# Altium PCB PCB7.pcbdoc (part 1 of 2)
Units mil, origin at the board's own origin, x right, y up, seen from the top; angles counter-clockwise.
Board outline 4082.91 x 5474.41 mil, 4 copper layers (Top Layer, Inner1, Inner2, Bottom Layer); 133 components, 162 nets, 570 pads, 328 vias.
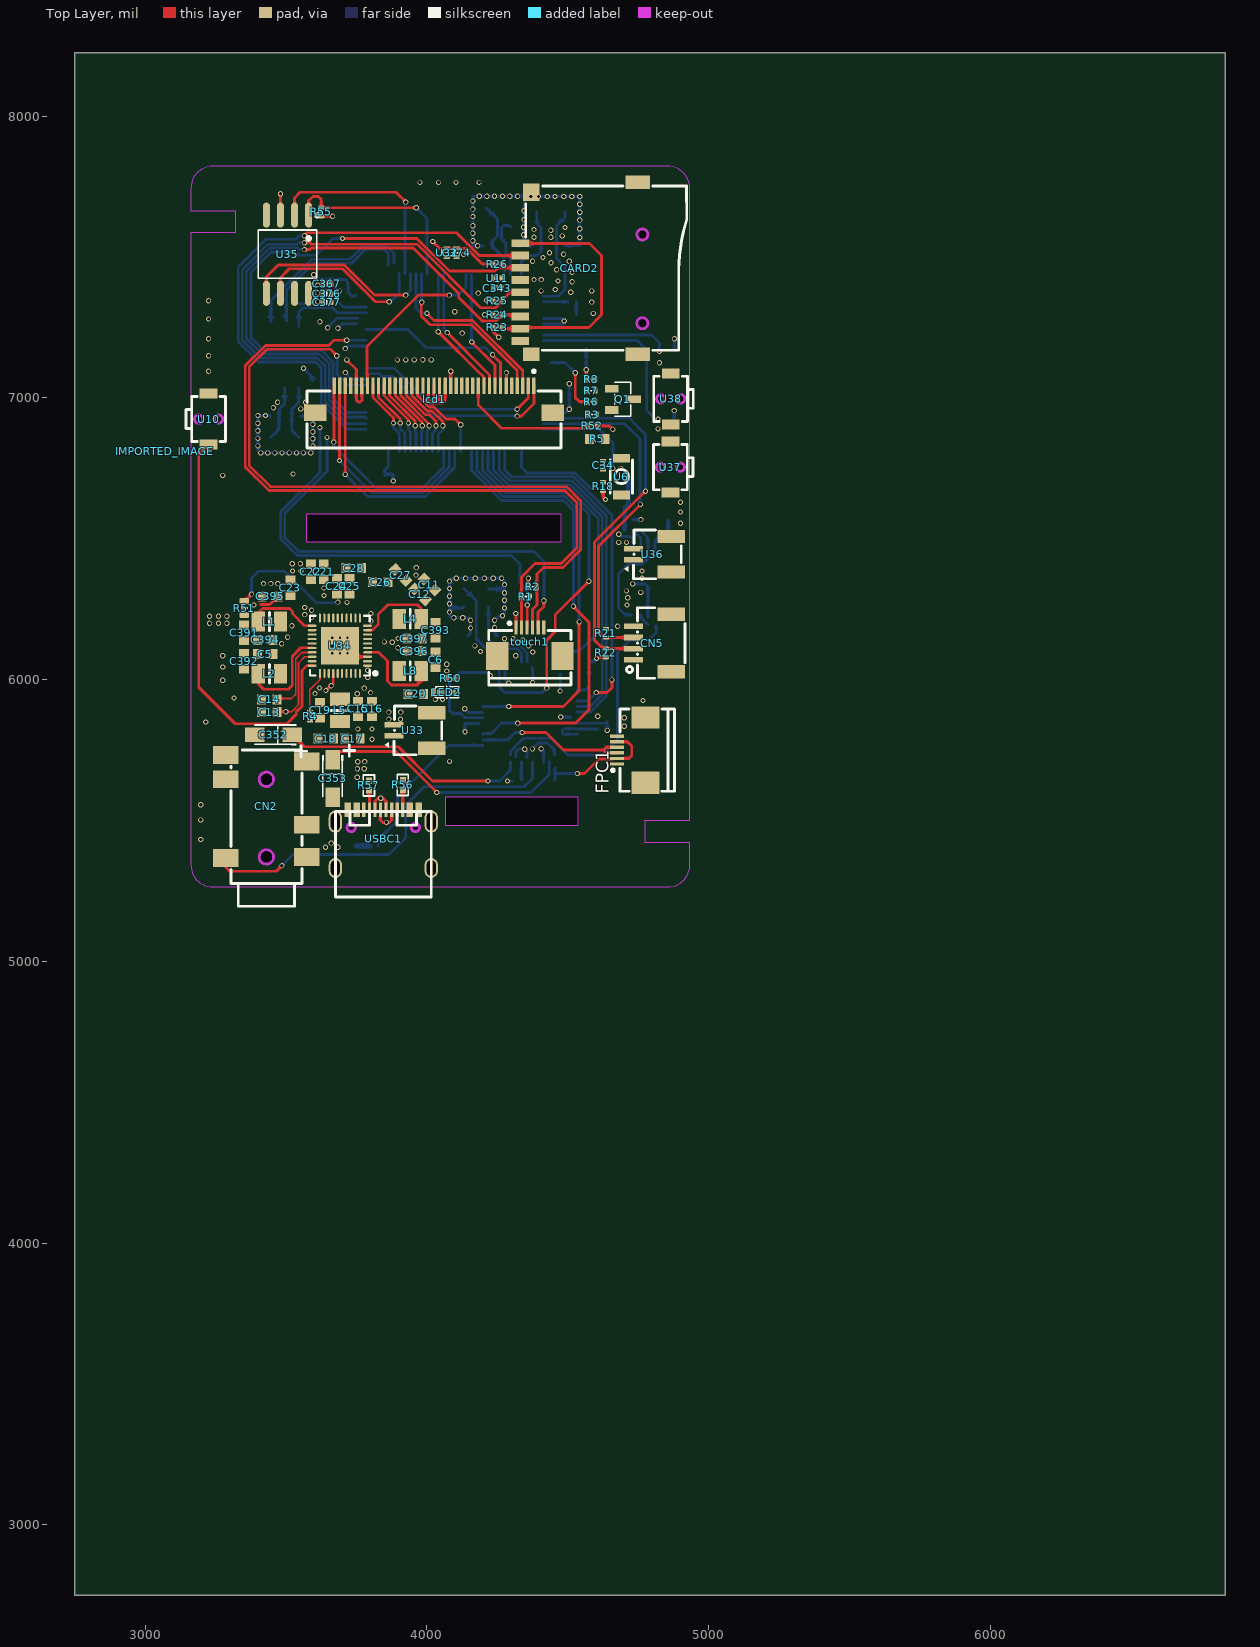
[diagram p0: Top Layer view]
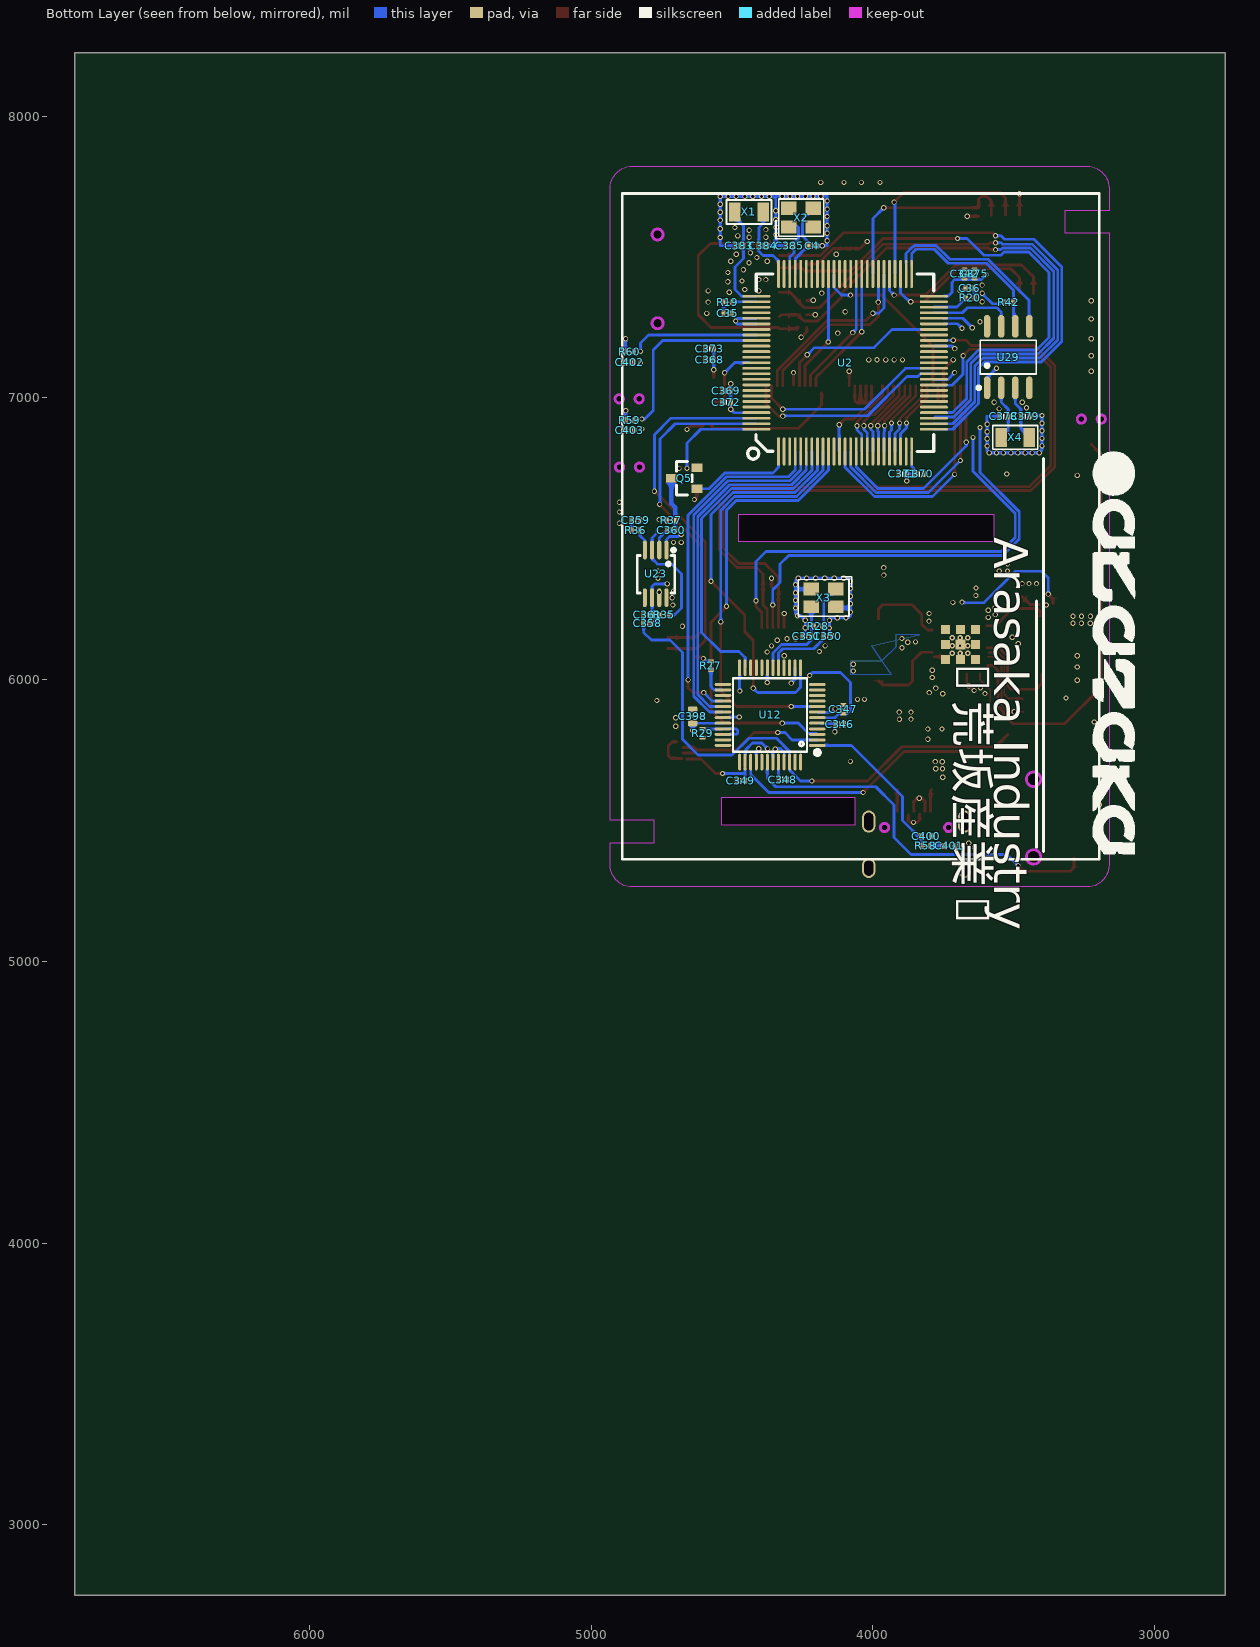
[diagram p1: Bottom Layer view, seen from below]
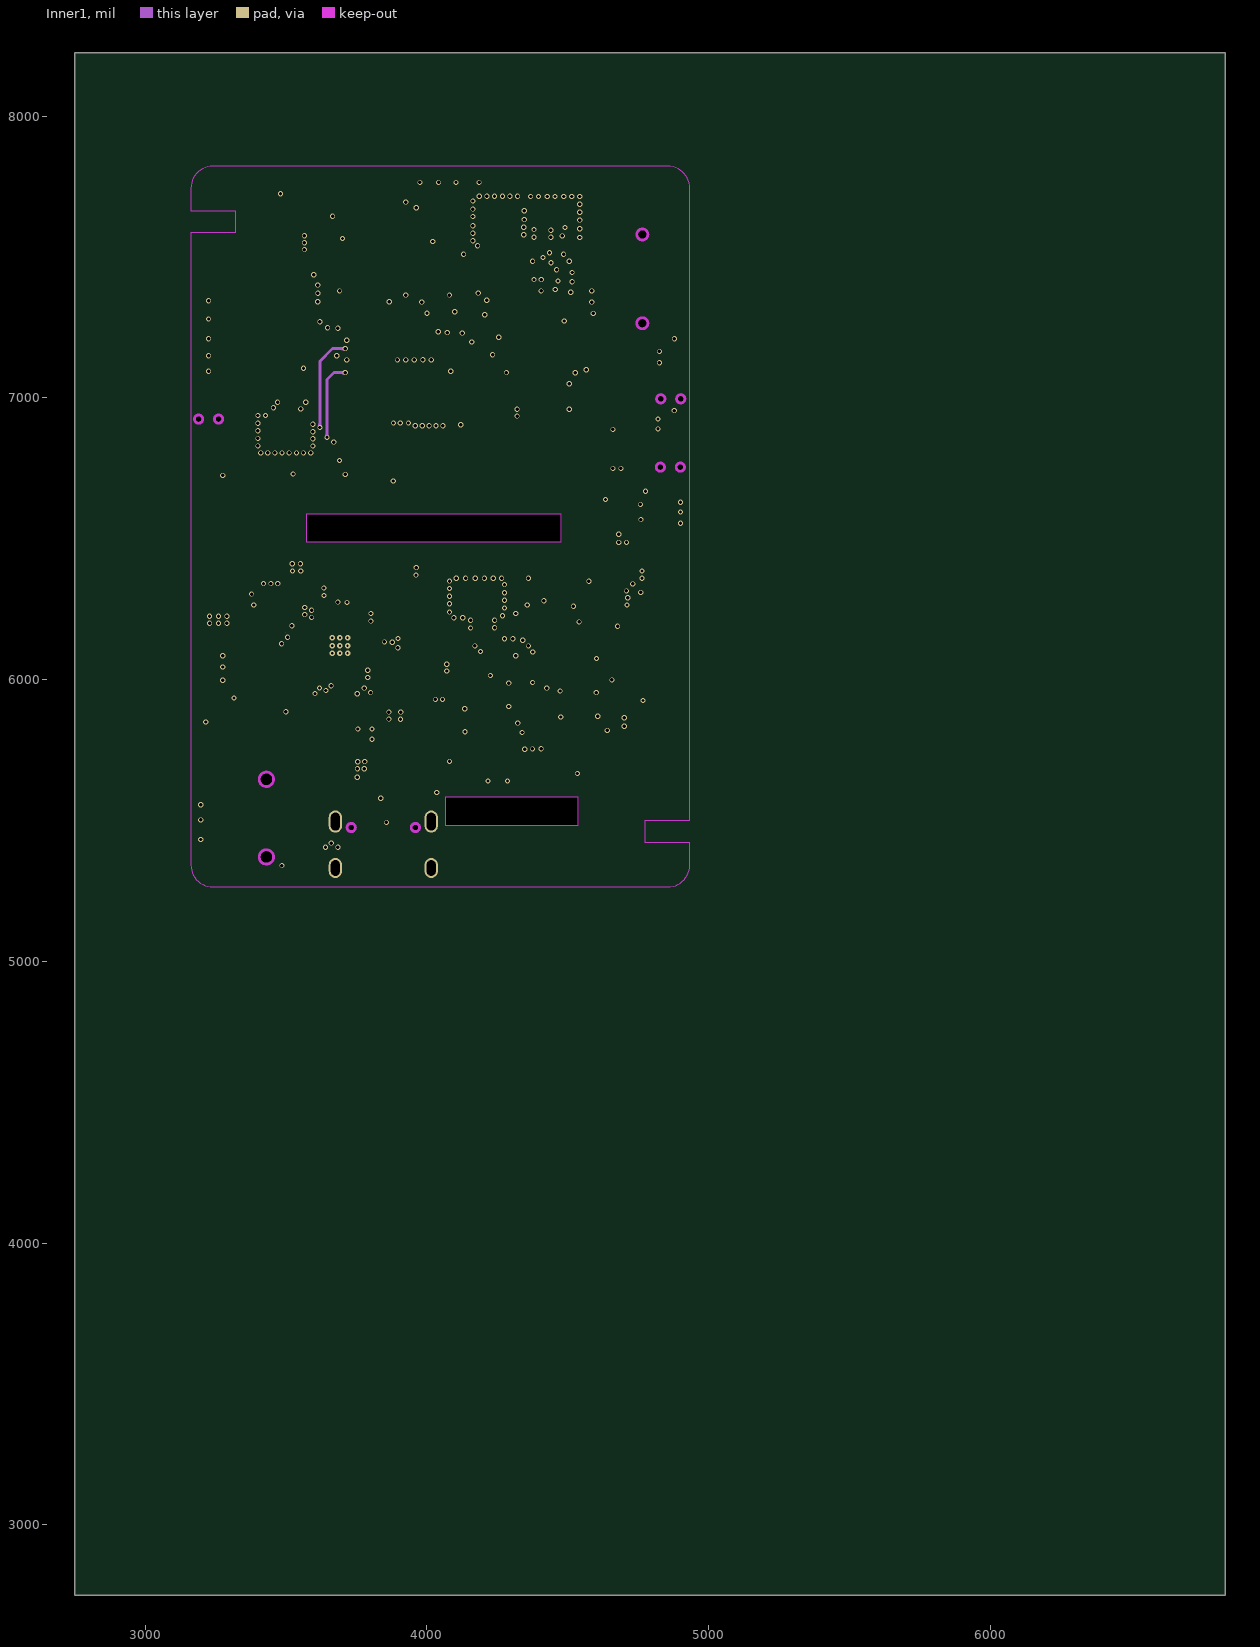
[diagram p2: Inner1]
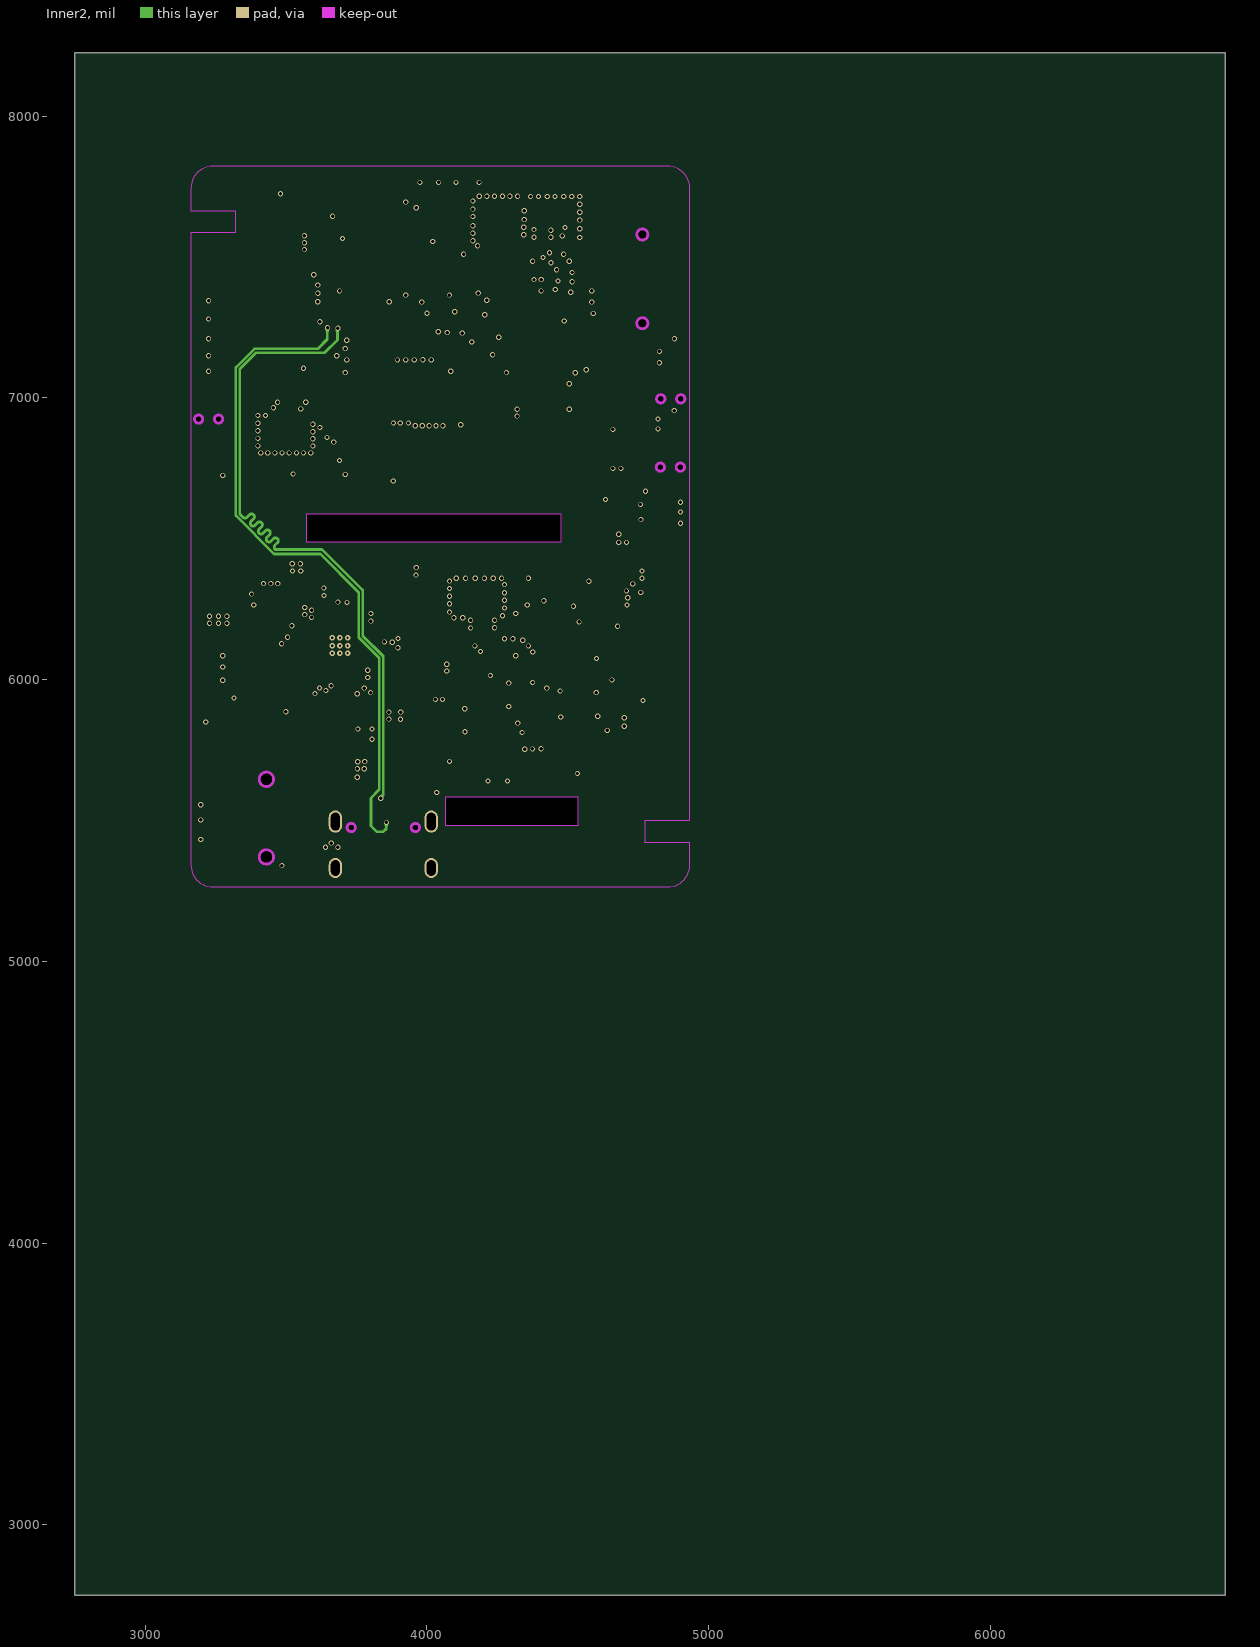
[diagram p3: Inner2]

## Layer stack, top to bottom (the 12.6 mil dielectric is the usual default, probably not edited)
Top Layer: signal copper (thickness not stored)
Dielectric: dielectric 12.6, FR-4, Dk 4.8
Inner1: signal copper (thickness not stored)
Dielectric: dielectric 12.6, FR-4, Dk 4.8
Inner2: signal copper (thickness not stored)
Dielectric: dielectric 12.6, FR-4, Dk 4.8
Bottom Layer: signal copper (thickness not stored)

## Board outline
6832.91,2750 2750,2750 2750,8224.41 6832.91,8224.41
cut-out: 4536.56,5581.38 4064.11,5581.38 4064.11,5482.95 4536.56,5482.95
cut-out: 4476.46,6586.51 3570.95,6586.51 3570.95,6488.08 4476.46,6488.08

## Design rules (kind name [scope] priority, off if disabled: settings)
Clearance copperThickness1oz [All] p1: gap=7 ignorepadtopadclearanceinfootprint=FALSE except(0: SMDPad-Via THPad-Via; 4: Track-Track; 6: Track-SMDPad SMDPad-SMDPad Track-THPad SMDPad-THPad THPad-THPad Track-Via Via-Via SMDPad-Fill THPad-Fill Via-Fill Fill-Fill Track-Region SMDPad-Region THPad-Region Via-Region Region-Region Track-Poly SMDPad-Poly THPad-Poly Via-Poly Fill-Poly Region-Poly Poly-Poly Track-Text SMDPad-Text THPad-Text Via-Text Fill-Text Region-Text Poly-Text Text-Text; 6.9: Track-Hole SMDPad-Hole THPad-Hole Via-Hole Fill-Hole Region-Hole Poly-Hole Text-Hole Sheet-Hole; 11.8: Track-Fill Fill-Region Track-Sheet SMDPad-Sheet THPad-Sheet Via-Sheet Fill-Sheet Region-Sheet Poly-Sheet Text-Sheet)
Clearance copperThickness2oz [All] p1: gap=7 ignorepadtopadclearanceinfootprint=FALSE except(6: Track-SMDPad SMDPad-SMDPad Track-THPad SMDPad-THPad THPad-THPad Track-Via SMDPad-Via THPad-Via Via-Via SMDPad-Fill THPad-Fill Via-Fill Fill-Fill Track-Region SMDPad-Region THPad-Region Via-Region Region-Region Track-Poly SMDPad-Poly THPad-Poly Via-Poly Fill-Poly Region-Poly Poly-Poly Track-Text SMDPad-Text THPad-Text Via-Text Fill-Text Region-Text Poly-Text Text-Text; 6.9: Track-Hole SMDPad-Hole THPad-Hole Via-Hole Fill-Hole Region-Hole Poly-Hole Text-Hole Sheet-Hole; 8: Track-Track; 11.8: Track-Fill Fill-Region Track-Sheet SMDPad-Sheet THPad-Sheet Via-Sheet Fill-Sheet Region-Sheet Poly-Sheet Text-Sheet)
DiffPairsRouting differentialPair [All] p1: maxuncoupledlength=10 maxlimit=6 mostfreqgap=6 toplayer_minwidth=5 toplayer_prefwidth=10 toplayer_maxwidth=100 bottomlayer_minwidth=5 bottomlayer_prefwidth=10 bottomlayer_maxwidth=100 midlayer1_minwidth=5 midlayer1_prefwidth=10 midlayer1_maxwidth=100 midlayer2_minwidth=5 midlayer2_prefwidth=10 midlayer2_maxwidth=100
PasteMaskExpansion pasteMaskExpansion [All] p1:
PlaneConnect innerPlane [All] p1: planeconnectstyle=Relief reliefexpansion=20 reliefentries=4 reliefconductorwidth=10 reliefairgap=10
PolygonConnect copperRegion [All] p1: connectstyle=Direct reliefentries=4 reliefconductorwidth=10 polygonreliefangle="90 Angle" airgapwidth=10
RoutingVias viaSize [All] p1: viastyle="Through Hole" holewidth=12 minholewidth=7 maxholewidth=248 width=18.5 minwidth=7 maxwidth=393.7
SolderMaskExpansion solderMaskExpansion [All] p1: useseparateexpansions=TRUE expansion=2 expansionbottom=2
Width copperThickness1oz [All] p1: maxlimit=100 minlimit=5 preferedwidth=10
Width copperThickness2oz [All] p1: maxlimit=100 minlimit=8 preferedwidth=10

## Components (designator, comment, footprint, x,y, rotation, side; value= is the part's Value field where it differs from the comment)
C4 "GRM1555C1H120JA01D" C0402-NSK#1 4215,7539.41 r180 bottom
C5 "CL10A225KP8NNNC" C0603 3425.63,6090.47 r180 top
C6 "CL10A226MQ8NRNC" C0603 4030.63,6070.47 r90 top
C11 "CL10A225KP8NNNC" C0603 4008.64,6337.2 r315 top
C12 "CL10A225KP8NNNC" C0603 3975.05,6302.2 r315 top
C13 "CL10A225KP8NNNC" C0603 3440,5884.41 r180 top
C14 "CL10A225KP8NNNC" C0603 3440,5929.41 r180 top
C15 "CL10A106KP8NNNC" C0603 3755.63,5895.47 r270 top
C16 "CL10A106KP8NNNC" C0603 3805.63,5895.47 r270 top
C17 "CL10B104KB8NNNC" C0603 3735.69,5790.3 r180 top
C18 "CL10A226MQ8NRNC" C0603 3640.63,5790.47 r0 top
C19 "CL10A225KP8NNNC" C0603 3620.63,5890.47 r90 top
C20 "CL10A105KO8NNNC" C0603 3960,5949.41 r180 top
C21 "CL10A225KP8NNNC" C0603 3633.64,6382.13 r270 top
C22 "CL10A225KP8NNNC" C0603 3588.07,6383.03 r270 top
C23 "CL10A225KP8NNNC" C0603 3515.63,6325.47 r90 top
C24 "CL10A225KP8NNNC" C0603 3680.63,6330.47 r270 top
C25 "CL10A225KP8NNNC" C0603 3725.63,6330.47 r270 top
C26 "CL10A475KP8NNNC" C0603 3834.09,6345.85 r180 top
C27 "CL10A225KP8NNNC" C0603 3906.66,6370.6 r315 top
C28 "CL10A225KP8NNNC" C0603 3740.63,6395.47 r0 top
C34 "CAP_0402" C0402-NSK#2 4624.79,6760.25 r270 top
C35 "CL05A105KA5NQNC" C0402-NSK#1 4515,7299.41 r0 bottom
C36 "CL05A105KA5NQNC" C0402-NSK#1 3655.63,7389.41 r180 bottom
C342 "CL05B104KB54PNC" C0402-NSK#1 3675,7439.41 r270 bottom
C343 "CL05B104KB54PNC" C0402-NSK#2 4250,7389.41 r0 top
C346 "CAP_0402" C0402-NSK#1 4117.33,5840.96 r0 bottom
C347 "CAP_0402" C0402-NSK#1 4105,5894.41 r270 bottom
C348 "CAP_0402" C0402-NSK#1 4320,5644.41 r180 bottom
C349 "CL05B103KB5NNNC" C0402-NSK#1 4468.65,5640.27 r0 bottom
C350 "GRM1555C1H120JA01D" C0402-NSK#1 4160,6154.41 r0 bottom
C351 "GRM1555C1H120JA01D" C0402-NSK#1 4235,6154.41 r180 bottom
C352 "TAJA106K016RNJ" CAP-SMD_L3.2-W1.6-RD-C7171 3455,5804.41 r180 top
C353 "TAJA106K016RNJ" CAP-SMD_L3.2-W1.6-RD-C7171 3665,5649.41 r270 top
C358 "CL05B104KB54PNC" C0402-NSK#1 4800,6199.41 r180 bottom
C359 "CL05B104KB54PNC" C0402-NSK#1 4841.3,6565.01 r0 bottom
C360 "CL05A105KA5NQNC" C0402-NSK#1 4716.3,6530.01 r180 bottom
C361 "CL05A105KA5NQNC" C0402-NSK#1 4800,6229.41 r180 bottom
C367 "CL05B104KB54PNC" C0402-NSK#2 3645,7404.41 r180 top
C368 "CL05B104KB54PNC" C0402-NSK#1 4580,7134.41 r180 bottom
C369 "CL05B104KB54PNC" C0402-NSK#1 4520,7024.41 r180 bottom
C370 "CL05B104KB54PNC" C0402-NSK#1 3835,6729.41 r0 bottom
C371 "CL05B104KB54PNC" C0402-NSK#1 3894.74,6729.67 r180 bottom
C372 "CL05A106MQ5NUNC" C0402-NSK#1 4520,6984.41 r180 bottom
C373 "CL05B104KB54PNC" C0402-NSK#1 4580,7174.41 r180 bottom
C374 "CL05B104KB54PNC" C0402-NSK#2 4105,7514.41 r90 top
C375 "CL05B104KB54PNC" C0402-NSK#1 3640,7439.41 r270 bottom
C376 "CL05B104KB54PNC" C0402-NSK#2 3645,7369.41 r180 top
C377 "CL05B104KB54PNC" C0402-NSK#2 3645,7339.41 r180 top
C378 "GRM1555C1H120JA01D" C0402-NSK#1 3535,6934.41 r180 bottom
C379 "GRM1555C1H120JA01D" C0402-NSK#1 3460,6934.41 r0 bottom
C383 "GRM1555C1H120JA01D" C0402-NSK#1 4475,7539.41 r0 bottom
C384 "GRM1555C1H120JA01D" C0402-NSK#1 4390,7539.41 r180 bottom
C385 "GRM1555C1H120JA01D" C0402-NSK#1 4295,7539.41 r0 bottom
C391 "CL10A226MQ8NRNC" C0603 3350.63,6165.47 r270 top
C392 "CL10A226MQ8NRNC" C0603 3350.63,6065.47 r90 top
C393 "CL10A226MQ8NRNC" C0603 4030.63,6175.47 r270 top
C394 "CL10A225KP8NNNC" C0603 3425.63,6140.47 r180 top
C395 "CL10A225KP8NNNC" C0603 3443.13,6294.89 r0 top
C396 "CL10A225KP8NNNC" C0603 3955.63,6100.47 r0 top
C397 "CL10A225KP8NNNC" C0603 3955.63,6145.47 r0 top
C398 "CL10A105KB8NNNC" "C0603 NSK"#1 4640,5869.41 r270 bottom
C400 "CL05B103KB5NNNC" C0402-NSK#3 3810,5444.41 r0 bottom
C401 "CL05A105KA5NQNC" C0402-NSK#3 3730,5409.41 r180 bottom
C402 "CL05A105KA5NQNC" C0402-NSK#1 4863.92,7126.24 r180 bottom
C403 "CL05A105KA5NQNC" C0402-NSK#1 4862.64,6885.4 r180 bottom
CARD2 "TF-115-BCP9" TF-SMD_TF-115-BCP9 4540,7459.41 r90 top
CN2 "PJ-342_C668606" AUDIO-SMD_PJ-342 3430,5549.41 r180 top
CN5 "WAFER-SH1.0-4PWB" CONN-SMD_4P-P1.00_WAFER-SH1.0-4PWB 4800,6129.41 r90 top
FPC1 "FPC-05F-6PH20" FPC-SMD_6P-P0.50_XUNPU_FPC-05F-6PH20 4725,5749.41 r90 top
IMPORTED_IMAGE "IMPORTED_IMAGE" IMPORTED_IMAGE 3070,6809.41 r0 top
L1 "1uH" L0806 3440.63,6205.47 r180 top
L2 "1uH" L0806 3440.63,6020.47 r180 top
L4 "1uH" L0806 3940.63,6215.47 r0 top
L5 "1uH" L0806 3690.63,5890.47 r90 top
L8 "1uH" L0806 3940.63,6030.47 r0 top
lcd1 "KH-FG0.5-H2.0-37PIN" FPC-SMD_37P-P0.50_KINGHELM_KH-FG0.5-H2.0-37PIN 4025,6994.41 r0 top locked
LED2 "NCD0402R1" LED0402-RD 4070,5954.41 r0 top
Q1 "MMS8050-H-TP" SOT-23-3_L2.9-W1.3-P1.90-LS2.4-BR 4695,6994.41 r180 top
Q5 "AO3401A_C15127" SOT-23_L2.9-W1.3-P1.90-LS2.4-BR 4670,6714.41 r180 bottom
R1 "0402WGF1002TCE" R0402#1 4350,6294.41 r0 top
R2 "0402WGF1002TCE" R0402#1 4375,6329.41 r180 top
R3 "0402WGF0000TCE" R0402#1 4587.4,6940.31 r0 top
R4 "0402WGF2200TCE" R0402#1 3585,5869.41 r270 top
R5 "CR164R33F" C0603 4605,6854.41 r180 top
R6 "0402WGF1001TCE" R0402#1 4582.4,6985.31 r0 top
R7 "0402WGF1002TCE" R0402#1 4582.4,7025.31 r0 top
R8 "0402WGF1002TCE" R0402#1 4582.4,7065.31 r0 top
R18 "Res_0402" R0402#1 4624.79,6685.25 r270 top
R19 "RC0402FR-0747RL" R0402#1 4515.29,7339.41 r180 bottom
R20 "RC0402FR-0747RL" R0402#1 3655,7354.41 r0 bottom
R21 "0402WGF4701TCE" R0402#1 4635,6164.41 r90 top
R22 "0402WGF4701TCE" R0402#1 4635,6094.41 r270 top
R23 "0402WGF1002TCE" R0402#1 4250,7249.41 r180 top
R24 "0402WGF1002TCE" R0402#1 4250,7294.41 r180 top
R25 "0402WGF1002TCE" R0402#1 4250,7344.41 r180 top
R26 "0402WGF1002TCE" R0402#1 4250,7474.41 r180 top
R27 "0402WGF1003TCE" R0402#1 4575,6049.41 r90 bottom
R28 "0402WGF1004TCE" R0402#1 4195,6189.41 r0 bottom
R29 "0402WGF1003TCE" R0402#1 4605,5809.41 r90 bottom
R35 "RC0402FR-0730KL" R0402#1 4740,6229.41 r180 bottom
R36 "RC0402FR-0730KL" R0402#1 4841.3,6530.01 r180 bottom
R37 "RC0402FR-0730KL" R0402#1 4716.3,6565.01 r0 bottom
R42 "Res_0402" R0402#1 3517.83,7338.28 r0 bottom
R50 "0402WGF2200TCE" R0402#1 4085,6004.41 r0 top
R51 "0603WAF0000T5E" "C0603 NSK"#2 3351.62,6253.69 r270 top
R52 "0402WGF0000TCE" R0402#1 4587.4,6900.31 r0 top
R55 "0402WGF5101TCE" R0402#1 3625,7659.41 r90 top
R56 "0402WGF5101TCE" R0402#2 3914.2,5625.85 r270 top
R57 "0402WGF5101TCE" R0402#2 3793.97,5623.95 r90 top
R58 "ERA2AEB431X" R0402#1 3812.08,5409.31 r180 bottom
R59 "0402WGF1002TCE" R0402#1 4862.33,6920.43 r0 bottom
R60 "0402WGF1002TCE" R0402#1 4863.03,7163.78 r0 bottom
touch1 "FPC-05F-6PH20" FPC-SMD_6P-P0.50_XUNPU_FPC-05F-6PH20 4365,6134.41 r0 top locked
U2 "FM33FK5X10" LQFP100 4335,6809.41 r90 bottom
U6 "TS2306A 200gf 002" SW-SMD_L3.0-W2.0-LS3.5 4689.79,6720.25 r270 top
U10 "THAF09-AC-R" KEY-SMD_L3.9-W2.9-P4.6-LS5.0-W3.6-EH 3225,6924.41 r270 top
U11 "HGC0402R5106M100NTEJ" C0402-NSK#2 4250,7424.41 r0 top
U12 "VS1053B-L" LQFP-48_L7.0-W7.0-P0.50-LS9.0-BL 4365,5874.41 r90 bottom
U23 "NS4150B_C189961" MSOP-8_L3.0-W3.0-P0.65-LS5.0-BL 4771.3,6375.01 r0 bottom
U29 "DS1302Z+T&R" SOIC-8_L4.9-W3.9-P1.27-LS6.0-BL 3520,7144.41 r180 bottom
U32 "HGC0402R5106M100NTEJ" C0402-NSK#2 4070,7514.41 r90 top
U33 "WAFER-SH1.0-2PWB" CONN-SMD_2P-P1.00_XUNPU_WAFER-SH1.0-2PWB 3950,5819.41 r90 top
U34 "AXP2101" QFN-40_L5.0-W5.0-P0.40-TL-EP3.4 3690.96,6120.1 r180 top
U35 "W25Q128JVSIQ_C113767" SOIC-8_L5.3-W5.3-P1.27-LS8.0-BL 3505,7509.41 r180 top
U36 "WAFER-SH1.0-2PWB" CONN-SMD_2P-P1.00_XUNPU_WAFER-SH1.0-2PWB 4800,6444.41 r90 top
U37 "THAF09-AC-R" KEY-SMD_L3.9-W2.9-P4.6-LS5.0-W3.6-EH 4863.91,6753.73 r90 top
U38 "THAF09-AC-R" KEY-SMD_L3.9-W2.9-P4.6-LS5.0-W3.6-EH 4865.2,6996.26 r90 top
USBC1 "HOST" USB-TYPE-C_16PIN-MALE-TYPE-C-31-M-12 3845,5434.41 r0 top
X1 "X321532768KGD2SI" OSC-SMD_L3.2-W1.5 4440,7659.41 r180 bottom
X2 "TAXM8M4RDBCCT2T" CRYSTAL-SMD_4P-L3.2-W2.5-BL 4255,7639.41 r180 bottom
X3 "TXM12.288M0004322FBCDO00T" CRYSTAL-SMD_4P-L3.2-W2.5-BL-2 4175,6289.41 r0 bottom
X4 "X321532768KGD2SI" OSC-SMD_L3.2-W1.5 3495,6859.41 r0 bottom

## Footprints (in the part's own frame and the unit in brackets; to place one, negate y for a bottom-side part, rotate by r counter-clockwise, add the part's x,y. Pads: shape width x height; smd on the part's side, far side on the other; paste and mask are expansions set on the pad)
AUDIO-SMD_PJ-342 [mm]
  rect 2.3x1.6 smd: 2(-3.65,4.55) 3(3.65,4.65) 4(-3.65,1.65) 5(3.65,-2.45) 6(-3.65,-4.05) 7(3.65,-4.65)
  Multi-Layer board cut-out: -0.65,4.55 -0.562,4.227 -0.324,3.99 0,3.904 0.324,3.99 0.562,4.227 0.65,4.55 0.65,4.55 0.562,4.873 0.324,5.109 0,5.196 -0.324,5.109 -0.562,4.873 -0.65,4.55
  Multi-Layer board cut-out: -0.65,-2.45 -0.562,-2.773 -0.324,-3.01 0,-3.096 0.324,-3.01 0.562,-2.773 0.65,-2.45 0.65,-2.45 0.562,-2.127 0.324,-1.891 0,-1.804 -0.324,-1.891 -0.562,-2.127 -0.65,-2.45
  Multi-Layer keep-out circle w0.254: c0,4.55 r0.65
  Multi-Layer keep-out circle w0.254: c0,-2.45 r0.65
  silkscreen extent -3.2,-5.1 3.2,8.99
C0402-NSK#1 [mil]
  rrect50% 15x22 smd: 1(-15,0) 2(15,0)
  silkscreen extent 0,-10 0,10
C0402-NSK#2 [mil]
  rrect45% 15x22 smd: 1(-15,0) 2(15,0)
  silkscreen extent 0,-10 0,10
C0402-NSK#3 [mil]
  rect 22x22 smd: 1(-19.99,0) 2(20.01,0)
  silkscreen extent 0,-5 0,6
C0603 [mm]
  rect 0.8x0.9 smd: 1(-0.7,0) 2(0.7,0)
"C0603 NSK"#1 [mil]
  rrect50% 22x33.47 smd: 1(-24.53,0) 2(24.53,0)
  silkscreen extent 0,-8 0,8
"C0603 NSK"#2 [mil]
  rrect35% 22x33.47 smd: 1(-24.53,0) 2(24.53,0)
  silkscreen extent 0,-8 0,8
CAP-SMD_L3.2-W1.6-RD-C7171 [mil]
  rect 69.19x51.02 smd: 1(-66.39,0) 2(66.39,0)
  silkscreen extent -118,-37 66,79
CONN-SMD_2P-P1.00_XUNPU_WAFER-SH1.0-2PWB [mm]
  rect 0.5x1.7 smd: 1(-0.5,1.7) 2(0.5,1.7)
  rect 1.2x2.5 smd: 3(1.6,-1.7) 4(-1.6,-1.7)
  silkscreen extent -2.2,-2.6 2.2,2.54
CONN-SMD_4P-P1.00_WAFER-SH1.0-4PWB [mm]
  rect 0.5x1.7 smd: 1(-1.5,1.7) 2(-0.5,1.7) 3(0.5,1.7) 4(1.5,1.7)
  rect 1.2x2.5 smd: 5(-2.6,-1.7) 6(2.6,-1.7)
  silkscreen extent -3.17,-2.95 3.17,2.32
CRYSTAL-SMD_4P-L3.2-W2.5-BL [mm]
  rect 1.4x1.2 smd: 1(-1.1,-0.85) 2(1.1,-0.85) 3(1.1,0.85) 4(-1.1,0.85)
  silkscreen extent -2.26,-1.91 2.03,1.68
CRYSTAL-SMD_4P-L3.2-W2.5-BL-2 [mm]
  rect 1.4x1.15 smd: 1(-1.1,-0.8) 2(1.1,-0.8) 3(1.1,0.8) 4(-1.1,0.8)
  silkscreen extent -2.54,-1.9 2.29,1.65
FPC-SMD_6P-P0.50_XUNPU_FPC-05F-6PH20 [mm]
  rect 0.3x1.25 smd: 1(-1.25,1.288) 2(-0.75,1.288) 3(-0.25,1.288) 4(0.25,1.288) 5(0.75,1.288) 6(1.25,1.288)
  rect 2x2.5 smd: 7(2.94,-1.288) 8(-2.94,-1.288)
  silkscreen extent -3.7,-3.91 3.7,1.78
FPC-SMD_37P-P0.50_KINGHELM_KH-FG0.5-H2.0-37PIN [mm]
  rect 0.3x1.5 smd: 1(9,1.225) 2(8.5,1.225) 3(8,1.225) 4(7.5,1.225) 5(7,1.225) 6(6.5,1.225) 7(6,1.225) 8(5.5,1.225) 9(5,1.225) 10(4.5,1.225) 11(4,1.225) 12(3.5,1.225) 13(3,1.225) 14(2.5,1.225) 15(2,1.225) 16(1.5,1.225) 17(1,1.225) 18(0.5,1.225) 19(0,1.225) 20(-0.5,1.225) 21(-1,1.225) 22(-1.5,1.225) 23(-2,1.225) 24(-2.5,1.225) 25(-3,1.225) 26(-3.5,1.225) 27(-4,1.225) 28(-4.5,1.225) 29(-5,1.225) 30(-5.5,1.225) 31(-6,1.225) 32(-6.5,1.225) 33(-7,1.225) 34(-7.5,1.225) 35(-8,1.225) 36(-8.5,1.225) 37(-9,1.225)
  rect 2x1.5 smd: 38(-10.7,-1.225) 39(10.7,-1.225)
  silkscreen extent -11.45,-4.38 11.45,2.65
IMPORTED_IMAGE [mil]
KEY-SMD_L3.9-W2.9-P4.6-LS5.0-W3.6-EH [mm]
  rect 0.9x1.6 smd: 1(-2.3,0) 2(2.3,0)
  Multi-Layer board cut-out: 0,1.275 -0.185,1.223 -0.32,1.086 -0.369,0.9 -0.32,0.714 -0.185,0.577 0,0.525 0,0.525 0.185,0.577 0.32,0.714 0.369,0.9 0.32,1.086 0.185,1.223 0,1.275
  Multi-Layer board cut-out: 0,-0.525 -0.185,-0.577 -0.32,-0.714 -0.369,-0.9 -0.32,-1.086 -0.185,-1.223 0,-1.275 0,-1.275 0.185,-1.223 0.32,-1.086 0.369,-0.9 0.32,-0.714 0.185,-0.577 0,-0.525
  Multi-Layer keep-out circle w0.254: c0,0.9 r0.375
  Multi-Layer keep-out circle w0.254: c0,-0.9 r0.375
  silkscreen extent -2.03,-2.03 2.03,1.52
L0806 [mm]
  rect 1.2x1.8 smd: 1(-1,0) 2(1,0)
  silkscreen extent 0,-0.83 0,0.83
LED0402-RD [mm]
  rect 0.636x0.54 smd: 1(-0.538,0) 2(0.538,0)
  silkscreen extent -1.39,-0.54 1.09,0.54
LQFP100 [mm]
  rect 2.54x0.25 smd: 1(0,0)
  oval 2.54x0.25 smd: 2(0,-0.5) 3(0,-1) 4(0,-1.5) 5(0,-2) 6(0,-2.5) 7(0,-3) 8(0,-3.5) 9(0,-4) 10(0,-4.5) 11(0,-5) 12(0,-5.5) 13(0,-6) 14(0,-6.5) 15(0,-7) 16(0,-7.5) 17(0,-8) 18(0,-8.5) 19(0,-9) 20(0,-9.5) 21(0,-10) 22(0,-10.5) 23(0,-11) 24(0,-11.5) 25(0,-12) 51(16,-12) 52(16,-11.5) 53(16,-11) 54(16,-10.5) 55(16,-10) 56(16,-9.5) 57(16,-9) 58(16,-8.5) 59(16,-8) 60(16,-7.5) 61(16,-7) 62(16,-6.5) 63(16,-6) 64(16,-5.5) 65(16,-5) 66(16,-4.5) 67(16,-4) 68(16,-3.5) 69(16,-3) 70(16,-2.5) 71(16,-2) 72(16,-1.5) 73(16,-1) 74(16,-0.5) 75(16,0)
  oval 0.25x2.54 smd: 26(2,-14) 27(2.5,-14) 28(3,-14) 29(3.5,-14) 30(4,-14) 31(4.5,-14) 32(5,-14) 33(5.5,-14) 34(6,-14) 35(6.5,-14) 36(7,-14) 37(7.5,-14) 38(8,-14) 39(8.5,-14) 40(9,-14) 41(9.5,-14) 42(10,-14) 43(10.5,-14) 44(11,-14) 45(11.5,-14) 46(12,-14) 47(12.5,-14) 48(13,-14) 49(13.5,-14) 50(14,-14) 76(14,2) 77(13.5,2) 78(13,2) 79(12.5,2) 80(12,2) 81(11.5,2) 82(11,2) 83(10.5,2) 84(10,2) 85(9.5,2) 86(9,2) 87(8.5,2) 88(8,2) 89(7.5,2) 90(7,2) 91(6.5,2) 92(6,2) 93(5.5,2) 94(5,2) 95(4.5,2) 96(4,2) 97(3.5,2) 98(3,2) 99(2.5,2) 100(2,2)
  silkscreen extent -0.69,-14 16,2.79
LQFP-48_L7.0-W7.0-P0.50-LS9.0-BL [mm]
  oval 0.27x1.5 smd: 1(-2.75,-4.25) 2(-2.25,-4.25) 3(-1.75,-4.25) 4(-1.25,-4.25) 5(-0.75,-4.25) 6(-0.25,-4.25) 7(0.25,-4.25) 8(0.75,-4.25) 9(1.25,-4.25) 10(1.75,-4.25) 11(2.25,-4.25) 12(2.75,-4.25) 25(2.75,4.25) 26(2.25,4.25) 27(1.75,4.25) 28(1.25,4.25) 29(0.75,4.25) 30(0.25,4.25) 31(-0.25,4.25) 32(-0.75,4.25) 33(-1.25,4.25) 34(-1.75,4.25) 35(-2.25,4.25) 36(-2.75,4.25)
  oval 1.5x0.27 smd: 13(4.25,-2.75) 14(4.25,-2.25) 15(4.25,-1.75) 16(4.25,-1.25) 17(4.25,-0.75) 18(4.25,-0.25) 19(4.25,0.25) 20(4.25,0.75) 21(4.25,1.25) 22(4.25,1.75) 23(4.25,2.25) 24(4.25,2.75) 37(-4.25,2.75) 38(-4.25,2.25) 39(-4.25,1.75) 40(-4.25,1.25) 41(-4.25,0.75) 42(-4.25,0.25) 43(-4.25,-0.25) 44(-4.25,-0.75) 45(-4.25,-1.25) 46(-4.25,-1.75) 47(-4.25,-2.25) 48(-4.25,-2.75)
  silkscreen extent -3.59,-4.46 3.3,3.34
MSOP-8_L3.0-W3.0-P0.65-LS5.0-BL [mil]
  oval 14.33x66.61 smd: 1(-38.39,-84.49) 2(-12.79,-84.49) 3(12.8,-84.49) 4(38.39,-84.49) 5(38.39,84.49) 6(12.8,84.49) 7(-12.79,84.49) 8(-38.39,84.49)
  silkscreen extent -69,-90 65,68
OSC-SMD_L3.2-W1.5 [mm]
  rect 1.05x1.7 smd: 1(-1.275,0) 2(1.275,0)
  silkscreen extent -2.03,-1.08 2.03,1.08
QFN-40_L5.0-W5.0-P0.40-TL-EP3.4 [mm]
  oval 0.8x0.2 smd: 1(-2.499,1.8) 2(-2.499,1.4) 3(-2.499,1) 4(-2.499,0.6) 5(-2.499,0.2) 6(-2.499,-0.2) 7(-2.499,-0.6) 8(-2.499,-1) 9(-2.499,-1.4) 10(-2.499,-1.8) 21(2.499,-1.8) 22(2.499,-1.4) 23(2.499,-1) 24(2.499,-0.6) 25(2.499,-0.2) 26(2.499,0.2) 27(2.499,0.6) 28(2.499,1) 29(2.499,1.4) 30(2.499,1.8)
  oval 0.2x0.8 smd: 11(-1.8,-2.499) 12(-1.4,-2.499) 13(-1,-2.499) 14(-0.6,-2.499) 15(-0.2,-2.499) 16(0.2,-2.499) 17(0.6,-2.499) 18(1,-2.499) 19(1.4,-2.499) 20(1.8,-2.499) 31(1.8,2.499) 32(1.4,2.499) 33(1,2.499) 34(0.6,2.499) 35(0.2,2.499) 36(-0.2,2.499) 37(-0.6,2.499) 38(-1,2.499) 39(-1.4,2.499) 40(-1.8,2.499)
  rect 3.4x3.4 smd: 41(0,0)
  silkscreen extent -3.35,-2.7 2.7,2.7
R0402#1 [mil]
  rrect50% 15x22 smd: 1(-15,0) 2(15,0)
  silkscreen extent -3,0 3,0
R0402#2 [mil]
  rect 22.27x21.26 smd: 1(-17.04,0) 2(17.04,0)
  silkscreen extent -37,-20 37,20
SOIC-8_L4.9-W3.9-P1.27-LS6.0-BL [mm]
  oval 0.588x2.045 smd: 1(-1.905,-2.772) 2(-0.635,-2.772) 3(0.635,-2.772) 4(1.905,-2.772) 5(1.905,2.772) 6(0.635,2.772) 7(-0.635,2.772) 8(-1.905,2.772)
  silkscreen extent -2.8,-2.92 2.53,1.52
SOIC-8_L5.3-W5.3-P1.27-LS8.0-BL [mm]
  oval 0.63x2.25 smd: 1(-1.905,-3.53) 2(-0.635,-3.53) 3(0.635,-3.53) 4(1.905,-3.53) 5(1.905,3.53) 6(0.635,3.53) 7(-0.635,3.53) 8(-1.905,3.53)
  silkscreen extent -2.82,-3.68 2.64,2.18
SOT-23-3_L2.9-W1.3-P1.90-LS2.4-BR [mm]
  rect 1.25x0.7 smd: 1(1,-0.95) 2(1,0.95) 3(-1,0)
  silkscreen extent -0.73,-1.53 0.73,1.53
SOT-23_L2.9-W1.3-P1.90-LS2.4-BR [mm]
  rect 1x0.8 smd: 1(1.15,-0.95) 2(1.15,0.95) 3(-1.15,0)
  silkscreen extent -0.7,-1.5 0.7,1.5
SW-SMD_L3.0-W2.0-LS3.5 [mil]
  rect 31.5x60 smd: 1(-64.98,0) 2(64.98,0)
  silkscreen extent -59,-39 59,39
TF-SMD_TF-115-BCP9 [mm]
  rect 0.7x1.6 smd: 1(2.25,5.3) 2(1.15,5.3) 3(0.05,5.3) 4(-1.05,5.3) 5(-2.15,5.3) 6(-3.25,5.3) 7(-4.35,5.3) 8(-5.45,5.3) 9(-6.55,5.3)
  rect 1.2x1.5 smd: 10(-7.75,4.3)
  rect 1.2x2.2 smd: 11(-7.75,-5.3) 13(7.75,-5.3)
  rect 1.6x1.5 smd: 12(6.85,4.3)
  Multi-Layer board cut-out: -4.95,-6.2 -4.703,-6.13 -4.524,-5.948 -4.458,-5.7 -4.524,-5.452 -4.703,-5.27 -4.95,-5.2 -4.95,-5.2 -5.197,-5.27 -5.376,-5.452 -5.442,-5.7 -5.376,-5.948 -5.197,-6.13 -4.95,-6.2
  Multi-Layer board cut-out: 3.05,-6.2 3.297,-6.13 3.476,-5.948 3.542,-5.7 3.476,-5.452 3.297,-5.27 3.05,-5.2 3.05,-5.2 2.803,-5.27 2.624,-5.452 2.558,-5.7 2.624,-5.948 2.803,-6.13 3.05,-6.2
  Multi-Layer keep-out circle w0.254: c-4.95,-5.7 r0.5
  Multi-Layer keep-out circle w0.254: c3.05,-5.7 r0.5
  silkscreen extent -7.38,-9.7 7.42,4.81
USB-TYPE-C_16PIN-MALE-TYPE-C-31-M-12 [mm]
  oval 1.2x1.8 hole 0.8 slot 1.4 at 90 deg: 0(-4.32,-2.624) 0(4.32,-2.624)
  oval 1.2x2 hole 0.8 slot 1.6 at 90 deg: 0(-4.32,1.556) 0(4.32,1.556)
  rect 0.3x1.3 smd: A1(-3.35,2.623) A4(-2.55,2.623) A5(-1.25,2.623) A6(-0.25,2.623) A7(0.25,2.623) A8(1.25,2.624) A9(2.55,2.623) A12(3.35,2.623) B1(3.05,2.623) B4(2.25,2.623) B5(1.75,2.623) B6(0.75,2.623) B7(-0.75,2.623) B8(-1.75,2.624) B9(-2.25,2.623) B12(-3.05,2.623)
  Multi-Layer board cut-out: -2.515,1.026 -2.567,1.211 -2.704,1.345 -2.89,1.394 -3.076,1.345 -3.213,1.211 -3.265,1.026 -3.265,1.026 -3.213,0.841 -3.076,0.706 -2.89,0.657 -2.704,0.706 -2.567,0.841 -2.515,1.026
  Multi-Layer board cut-out: 3.265,1.026 3.213,1.211 3.076,1.345 2.89,1.394 2.704,1.345 2.567,1.211 2.515,1.026 2.515,1.026 2.567,0.841 2.704,0.706 2.89,0.657 3.076,0.706 3.213,0.841 3.265,1.026
  Multi-Layer keep-out circle w0.254: c-2.89,1.026 r0.375
  Multi-Layer keep-out circle w0.254: c2.89,1.026 r0.375
  silkscreen extent -4.32,-5.23 4.32,2.47

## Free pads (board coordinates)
  rect 31.5x31.5 smd far side: 31(3636.56,6070.88) 31(3636.56,6123.8) 31(3636.56,6176.95) 31(3689.71,6070.88) 31(3689.71,6176.95) 31(3742.47,6070.88) 31(3742.47,6123.8) 31(3742.47,6176.95)
  rect 35.43x35.43 smd far side: 31(3689.43,6123.68)

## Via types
v1: diameter 18.5, hole 12, Top Layer to Bottom Layer, 319 vias
v2: diameter 19.7, hole 7.9, Top Layer to Bottom Layer, 9 vias

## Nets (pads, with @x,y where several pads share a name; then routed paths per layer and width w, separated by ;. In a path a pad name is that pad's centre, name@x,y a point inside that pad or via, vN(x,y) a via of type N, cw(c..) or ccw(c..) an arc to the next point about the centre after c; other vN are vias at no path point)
$1N8397: C384.1 U2.75 X1.2 | length 275.9
  Bottom Layer w10: U2.75@4335,7439.33 4335,7484.41 4355,7504.41 4390,7504.41 4405,7519.41 C384.1@4405,7539.41 4405,7604.41 4389.8,7619.61 X1.2@4389.8,7659.41
$1N8398: C383.1 U2.76 X1.1 | length 386.1
  Bottom Layer w10: U2.76@4413.74,7360.59 4466.18,7360.59 4490,7384.41 4490,7464.41 4460,7494.41 C383.1@4460,7539.41 4460,7609.41 4490.2,7639.61 X1.1@4490.2,7659.41
$1N8586: C35.2 R19.1 | length 45.1
  Bottom Layer w10: C35.2@4530,7294.41 4530.29,7294.7 R19.1@4530.29,7339.41
$1N8587: C36.2 R20.1 | length 35.3
  Bottom Layer w10: R20.1@3640,7354.41 3640.63,7355.04 C36.2@3640.63,7389.41
$1N8688: CARD2.1 CARD2.8 R23.1 | length 894.1
  Top Layer w10: R23.1@4265,7249.41 4269.57,7244.84 CARD2.8@4331.34,7244.84 4335.91,7249.41 4575,7249.41 4620,7294.41 4620,7504.41 4576.42,7547.99 CARD2.1@4331.34,7547.99
$1N9003: C378.2 U29.2 X4.2 | length 196.6
  Bottom Layer w10: U29.2@3545,7035.26 3545,6984.41 3520,6959.41 C378.2@3520,6934.41 3520,6884.61 X4.2@3545.2,6859.41
$1N9004: C379.2 U29.3 X4.1 | length 196.6
  Bottom Layer w10: X4.1@3444.8,6859.41 3475,6889.61 C379.2@3475,6934.41 3475,6959.41 3495,6979.41 U29.3@3495,7035.26
$1N13562: Q1.3 R5.1
$1N13566: Q1.1 R6.2 R7.2 R8.2
$1N19277: R56.2 USBC1.B5 | length 77.1
  Top Layer w10: R56.2@3912.96,5609.41 3913.9,5608.47 USBC1.B5@3913.9,5532.69
$1N19279: R57.1 USBC1.A5 | length 78.3
  Top Layer w10: R57.1@3792.04,5609.41 3795.79,5605.66 USBC1.A5@3795.79,5532.69
$2N1132: LED2.2 R50.2
$2N7324: L1.1 U34.22
  other v1: 3520.63,6190.47
$2N7333: L2.1 U34.25
$2N7338: L8.1 U34.5
$2N7343: L4.1 U34.8
$2N7384: L5.2 U34.35
$2N7386: C20.2 U34.2
$3N2174: R27.1 U12.26 | length 107.4
  Bottom Layer w10: U12.26@4532.32,5962.99 4563.58,5962.99 4575,5974.41 R27.1@4575,6034.41
$3N2188: C350.2 R28.1 U12.17 X3.1 | length 409.6
  Bottom Layer w10: X3.1@4131.69,6320.9 4133.51,6320.9 4162.86,6291.55 4163.81,6291.55 4170.25,6285.11 4170.25,6284.16 4175,6279.41 4175,6144.41 4210,6109.41 4320,6109.41 4335.47,6093.94 U12.17@4335.47,6061.73
$3N2200: C348.1 U12.44 | length 62.9
  Bottom Layer w10: C348.1@4335,5644.41 4335,5706.62 U12.44@4335.47,5707.09
$3N2241: R36.2 U23.4 | length 77.4
  Bottom Layer w10: U23.4@4809.69,6459.5 4809.69,6493.4 4826.3,6510.01 R36.2@4826.3,6530.01
$3N2242: R35.2 U23.3 | length 410.7
  Bottom Layer w10: R35.2@4725,6229.41 4705,6229.41 4680,6254.41 4680,6374.41 4715,6409.41 4765,6409.41 4784.1,6428.51 U23.3@4784.1,6459.5 4784.1,6502.21 4766.3,6520.01 4766.3,6530.01
$3N2243: C359.2 R36.1 | length 35
  Bottom Layer w14: R36.1@4856.3,6530.01 C359.2@4856.3,6565.01
$3N2244: C358.2 R35.1 | length 47.4
  Bottom Layer w10: R35.1@4755,6229.41 4755,6224.41 C358.2@4785,6194.41
$3N2251: C360.1 U23.2 | length 81.8
  Bottom Layer w10: C360.1@4731.3,6530.01 4758.51,6502.8 U23.2@4758.51,6459.5
$3N2275: C351.2 R28.2 U12.18 X3.3 | length 305.6
  Bottom Layer w10: X3.3@4218.31,6257.91 4218.31,6141.1 4235,6124.41 4325,6124.41 4355,6094.41 4355,6061.89 U12.18@4355.16,6061.73
$3N2311: C360.2 Q5.3 R37.1 | length 185.2
  Bottom Layer w14: C360.2@4701.3,6530.01 R37.1@4701.3,6565.01
  Bottom Layer w16: R37.1@4701.3,6565.01 4701.3,6610.71 4715.28,6624.69 Q5.3@4715.28,6709.41
$3N5130: U23.5 U36.1
  other v1: 4763.1,6359.68 4763.38,6385.24
$3N5134: U23.8 U36.2
  other v1: 4710,6264.41 4712.91,6290.06 4707.91,6314.65 4680.53,6486.71 4708.15,6486.71
$3N6131: C401.2 CN2.2
  other v1: 3640,5404.41 3683.86,5404.41 3660,5419.41
$3N6419: C401.1 R58.2 | length 47.1
  Bottom Layer w18: C401.1@3749.99,5409.41 3750.1,5409.31 R58.2@3797.08,5409.31
ALDO1: C22.2 C346.2 U12.5 U12.7 U12.24 U12.31 U34.18 | length 242.8
  Bottom Layer w10: C346.2@4132.33,5840.96 4135,5838.29 v1(4135,5814.41) ; v1(4133.96,5896.3) 4147.5,5882.76 U12.7@4196.53,5882.76 ; C346.2@4136.04,5844.96 4136.92,5844.09 4184.8,5844.09 U12.5@4185.66,5844.94 ; v1(4472.43,5959.04) 4473.53,5960.15 U12.24@4473.53,6020.06 ; v1(4474.84,5866.84) U12.31@4509.94,5866.84
  other v1: 3522.73,6385.03 3551.8,6385.27 3522.02,6410.56 3550.86,6411.03
ALDO2: C23.2 U34.19
ALDO3: C24.2 C349.1 FPC1.2 FPC1.5 R51.1 U12.38 U12.43 U12.45 U34.16 | length 1056.1
  Top Layer w10: R51.1@3360.76,6269.38 3360.76,6286.2 v1(3377.58,6303.02) ; v1@4374.1,5751.76 v1(4374.1,5753.89) ; v1(4533.99,5666.42) 4558.58,5666.42 4610.43,5718.27 FPC1.2@4660.68,5718.27 ; FPC1.2@4678.31,5719.65 4678.7,5720.04 4716.87,5720.04 4726.6,5729.78 4726.6,5763.66 4711.03,5779.24 FPC1.5@4697.01,5779.24
  Bottom Layer w10: v1(3377.58,6303.02) 3377.58,6359.54 3402.48,6384.43 3494.65,6384.43 3606.34,6272.75 v1@3685.06,6272.75 ; U12.45@4315.12,5727.14 4315.12,5742.04 4327.95,5754.87 4344.43,5754.87 4355.11,5744.2 4355.11,5724.34 U12.43@4354.83,5724.07 ; v1(4374.1,5753.89) 4394.62,5774.41 4428.03,5774.41 4451.74,5750.7 U12.38@4451.74,5733.33 ; C349.1@4451.92,5643.1 4454.05,5645.23 U12.38@4454.05,5685.64 ; 4456.48,5666.42 v1(4533.99,5666.42) 4536.84,5666.42 v1@4537.02,5666.6
  other v1: 4346.97,5752.43 3683.9,6274.64
ALDO4: C25.2 U34.15
  other v1: 3716.27,6273.76
AUDIO_KEY: Q5.1 U2.1 | length 377.4
  Bottom Layer w10: U2.1@4335,6809.41 4335,6753.41 4355,6733.41 4526,6733.41 4582.4,6677.01 Q5.1@4624.72,6677.01
BL: R6.1 U2.88 | length 236.9
  Top Layer w10: v1(4526.42,7088.69) 4526.42,7000.19 4540.33,6986.28 R6.1@4568.15,6986.28
  Bottom Layer w10: U2.88@4440.45,7124.73 4490.39,7124.73 v1(4526.42,7088.69)
BLDO1: C27.2 U34.12
BLDO2: C28.2 U34.14
BLDOIN: C26.2 U34.13
CE: U2.52 U29.5 | length 642.1
  Bottom Layer w10: U29.5@3444.93,7268.49 3445.99,7269.56 3445.99,7346.29 3591.32,7491.61 3727.18,7491.61 3776.56,7540.94 3853.11,7540.94 3858.29,7535.76 3859.2,7535.76 3883.02,7511.94 U2.52@3883.02,7477.73
CHGLED: LED2.1 U34.1
  other v1: 4030,5929.41 4055,5929.41 3789.63,6006.95 3789.63,6032.75
CLK: CARD2.5 R25.1 U2.27 | length 2031
  Top Layer w10: v1(3565,7550.36) 3584.25,7550.36 3589.5,7545.11 3964.1,7545.11 4189.8,7319.41 4243.01,7319.41 R25.1@4266.04,7342.45 ; R25.1@4265,7344.41 4295.35,7374.76 CARD2.5@4331.34,7374.76
  Bottom Layer w10: v1(3565,7550.36) 3545.75,7550.36 3540.5,7545.11 3435.7,7545.11 3344.4,7453.81 3344.4,7205.41 3408.4,7141.41 3610,7141.41 3639,7112.41 3639,6985.81 3716.98,6907.83 U2.27@3783.82,6907.83
CPUS_LDO: C11.1 U34.10
  other v1: 3801.11,6207.44 3800.85,6234.09 3961.18,6370.69 3961.95,6397.09
CS: CARD2.2 U2.26 | length 2006.6
  Top Layer w10: v1(3565,7574.86) 3575.75,7585.61 4104.79,7585.61 4185.72,7504.68 CARD2.2@4331.34,7504.68
  Bottom Layer w10: v1(3565,7574.86) 3545.25,7574.86 3533.18,7562.79 3428.38,7562.79 3330,7464.41 3330,7200.01 3402.6,7127.41 3604.2,7127.41 3625,7106.61 3625,6980.01 3716.86,6888.15 U2.26@3783.82,6888.15
DB0: lcd1.1 U2.36 | length 740.3
  Top Layer w10: v1(4320,6934.91) 4335.5,6934.91 4380,6979.41 4380,7041.96 lcd1.1@4379.32,7042.64
  Bottom Layer w10: U2.36@3783.82,7085 3831.73,7085 3840.98,7075.75 3878.86,7075.75 4018.45,6936.16 4318.75,6936.16 v1(4320,6934.91)
DB1: lcd1.2 U2.37 | length 696
  Top Layer w10: v1(4320,6959.41) 4359.65,6999.05 lcd1.2@4359.65,7042.64
  Bottom Layer w10: U2.37@3783.82,7104.69 3784.09,7104.41 3885,7104.41 4030,6959.41 v1(4320,6959.41)
DB2: lcd1.3 U2.56 | length 645.7
  Top Layer w10: v1(4000.25,7299.64) 4025.48,7274.41 4162.03,7274.41 4339.95,7096.49 lcd1.3@4339.95,7042.64
  Bottom Layer w10: U2.56@3960.98,7439.33 3960.98,7318.43 3979.77,7299.64 v1(4000.25,7299.64)
DB3: lcd1.4 U2.57 | length 624.6
  Top Layer w10: v1(3981.23,7339.64) 3980,7338.4 3980,7289.41 4010,7259.41 4157.23,7259.41 4320.27,7096.37 lcd1.4@4320.27,7042.64
  Bottom Layer w10: U2.57@3980.67,7439.33 3980.67,7340.2 v1(3981.23,7339.64)
DB4: lcd1.22 U2.12 | length 327.1
  Top Layer w10: lcd1.22@3965.95,7042.64 3965.95,7008.26 4006.8,6967.41 4024.23,6967.41 4067.23,6924.41 4100,6924.41 v1(4120,6904.41)
  Bottom Layer w10: U2.12@4118.47,6809.41 4120,6810.94 v1(4120,6904.41)
DB5: lcd1.35 U2.13 | length 834.7
  Top Layer w10: lcd1.35@3710.05,7042.64 3710,6728.27 v1(3710.21,6728.06)
  Bottom Layer w10: v1(3710.21,6728.06) 3788.86,6649.41 3994.6,6649.41 4098.78,6753.59 U2.13@4098.78,6809.41
DB6: lcd1.36 U2.14 | length 795.5
  Top Layer w10: v1(3689.75,6777.16) 3689.75,7041.49 3689.48,7041.76 lcd1.36@3690.36,7042.64
  Bottom Layer w10: v1(3689.75,6777.16) 3803.5,6663.41 3988.8,6663.41 4079.09,6753.71 U2.14@4079.09,6809.41
DB7: lcd1.37 U2.15 | length 754.7
  Top Layer w10: v1(3669.23,6842.67) 3670,6843.44 3670,7041.96 lcd1.37@3670.68,7042.64
  Bottom Layer w10: v1(3669.23,6842.67) 3669.23,6828.53 3820.34,6677.41 3983,6677.41 4059.41,6753.82 U2.15@4059.41,6809.41
DB8: lcd1.23 U2.16 | length 295.8
  Top Layer w10: lcd1.23@3946.26,7042.64 3947.5,7041.4 3947.5,7006.91 4001,6953.41 4017.84,6953.41 4056.58,6914.67 v1(4056.58,6900.53)
  Bottom Layer w10: U2.16@4039.72,6809.41 4039.72,6869.13 4056.58,6885.99 v1(4056.58,6900.53)
DB9: lcd1.24 U2.17 | length 290.2
  Top Layer w10: lcd1.24@3926.57,7042.64 3926.57,7008.04 3995.2,6939.41 4009.34,6939.41 4032.08,6916.68 v1(4032.08,6900.53)
  Bottom Layer w10: U2.17@4020.04,6809.41 4020.04,6874.45 4032.08,6886.49 v1(4032.08,6900.53)
DB10: lcd1.25 U2.18 | length 277.9
  Top Layer w10: lcd1.25@3906.89,7042.64 3906.89,7007.92 4007.58,6907.23 v1(4007.58,6900.53)
  Bottom Layer w10: U2.18@4000.35,6809.41 4000.35,6879.76 4007.58,6886.99 v1(4007.58,6900.53)
DB11: lcd1.26 U2.19 | length 273.9
  Top Layer w10: lcd1.26@3887.2,7042.64 3887.2,7007.81 3983.08,6911.94 v1(3983.08,6900.53)
  Bottom Layer w10: U2.19@3980.67,6809.41 3980.67,6880.08 3983.08,6882.49 v1(3983.08,6900.53)
DB12: lcd1.27 U2.20 | length 271.9
  Top Layer w10: lcd1.27@3867.53,7042.64 3867.53,7007.69 3958.58,6916.64 v1(3958.58,6900.53)
  Bottom Layer w10: v1(3958.58,6900.53) 3958.58,6880.83 3960.98,6878.43 U2.20@3960.98,6809.41
DB13: lcd1.28 U2.21 | length 271.9
  Top Layer w10: lcd1.28@3847.84,7042.64 3847.84,7007.58 3934.08,6921.34 v1(3934.08,6910.53)
  Bottom Layer w10: v1(3934.08,6910.53) 3934.08,6885.33 3941.3,6878.11 U2.21@3941.3,6809.41
DB14: lcd1.29 U2.22 | length 271.9
  Top Layer w10: lcd1.29@3828.16,7042.64 3828.16,7001.25 3905.33,6924.08 v1(3905.33,6910.53)
  Bottom Layer w10: v1(3905.33,6910.53) 3905.33,6888.88 3921.61,6872.59 U2.22@3921.61,6809.41
DB15: lcd1.30 U2.23 | length 271.9
  Top Layer w10: lcd1.30@3808.47,7042.64 3808.47,7001.15 3880.83,6928.78 v1(3880.83,6910.53)
  Bottom Layer w10: v1(3880.83,6910.53) 3880.83,6893.58 3901.93,6872.48 U2.23@3901.93,6809.41
DC1SW: C395.1 U34.20
  other v1: 3590.63,6220.47 3566.11,6230.47 3590.63,6245.47 3566.37,6255.47 3419.8,6340.47 3446.2,6340.47 3470.63,6340.47
DC4SW: C12.1 U34.11
DCDC1: C342.2 C343.2 C347.2 C367.2 C368.2 C369.2 C370.2 C371.2 C372.2 C373.2 C374.2 C375.2 C376.2 C377.2 C391.1 C398.2 CARD2.4 CN5.4 L1.2 lcd1.6 lcd1.16 lcd1.32 lcd1.33 R1.2 R2.2 R8.1 R18.2 R21.2 R22.2 R23.2 R24.2 R25.2 R26.2 R27.2 R37.2 R42.2 R51.2 R52.2 R55.1 R59.2 R60.2 touch1.1 U2.25 U2.50 U2.80 U2.81 U2.97 U11.2 U12.6 U12.14 U12.19 U12.32 U23.1 U29.1 U32.2 U34.21 U35.3 U35.7 U35.8 | length 3061.8
  Top Layer w10: L1.2@3408.04,6226.04 3406.38,6227.7 3406.38,6241.84 3416.44,6251.9 3512.34,6251.9 3522.34,6241.9 3522.34,6233.75 3565.43,6190.67 U34.21@3595.3,6190.67 ; U35.3@3480,7648.39 v1(3480,7724.41) ; R55.1@3625,7644.41 v1(3665,7644.41) ; v1(3715,7134.41) 3749.41,7099.99 lcd1.33@3749.41,7042.64 3749.41,6989.99 3755,6984.41 3762.22,6984.41 3769.09,6991.29 lcd1.32@3769.09,7042.64 ; v1(4020.6,7554.41) 4045.6,7529.41 4075,7529.41 4141.19,7529.41 4196.19,7474.41 R26.2@4235,7474.41 ; lcd1.16@4084.05,7042.64 v1(4084.05,7094.41) ; v1(4205,7294.41) R24.2@4235,7294.41 ; v1(4211.92,7346.33) 4233.08,7346.33 R25.2@4235,7344.41 ; R23.2@4235,7249.41 4235,7234.41 v1(4255,7214.41) ; lcd1.6@4281.98,7046.37 v1(4281.98,7089.17) ; v1(4315,6234.41) 4315.79,6233.62 touch1.1@4315.79,6185.1 ; R2.2@4360,6329.41 v1(4360,6359.41) ; R8.1@4565.22,7071.81 v1(4565.22,7099.1) ; v1(4601.75,6074.41) 4606.75,6079.41 R22.2@4635,6079.41 ; R52.2@4602.4,6900.31 4647.28,6900.31 v1(4660,6887.58) ; R18.2@4625.44,6672.66 4625.44,6647.29 v1(4633.64,6639.09)
  Bottom Layer w10: R42.2@3527.81,7333.68 3575.92,7333.68 v1(3612.8,7370.57) ; v1(3561.77,7104.75) 3595.31,7071.2 U29.1@3595.31,7061.35 ; v1(3598.48,7436.32) 3615.39,7419.41 3710,7419.41 3720,7409.41 3720,7374.41 3732.89,7361.52 U2.50@3747.88,7361.52 ; C370.2@3850.78,6725.81 3850.78,6744.26 3862.57,6756.05 U2.25@3862.56,6809.41 ; C370.2@3851.8,6723.5 3857.26,6728.96 3874.54,6728.96 C371.2@3880,6723.5 ; C371.2@3879.74,6729.67 3880,6729.41 C371.2@3880,6723.5 ; v1(3880,6704.66) C371.2@3880,6723.5 ; U12.6@4197.68,5864.57 4134.84,5864.57 4120,5879.41 C347.2@4105,5879.41 4090,5879.41 4080,5889.41 4080,5989.41 4115,6024.41 4215,6024.41 v1(4225,6014.41) ; U12.14@4276.42,6041.73 4276.42,6000.92 v1(4290,5987.34) ; U12.19@4374.84,6041.73 4375,6041.57 v1(4375,5989.41) ; U2.81@4413.74,7262.17 4482.76,7262.17 4487.5,7266.91 4487.5,7276.91 4482.56,7281.85 U2.80@4413.74,7281.85 ; U2.97@4428.56,6946.57 4492.16,6946.57 v1(4505,6959.41) C372.2@4505,6984.41 C369.2@4505,7024.41 v1(4505,7049.41) ; U12.32@4532.32,5844.88 C398.2@4635,5844.88 ; C373.2@4565,7174.41 C368.2@4565,7134.41 4565,7099.32 v1(4565.22,7099.1) ; R27.2@4575,6064.41 4595,6064.41 v1@4605,6074.41 ; C398.2@4637.5,5847.38 C398.2@4640,5849.88 ; v1(4640,5819.41) C398.2@4640,5844.88 ; v1(4680.35,6515.86) 4683.37,6515.86 4691.22,6508.01 4721.4,6508.01 4732.91,6496.5 U23.1@4732.91,6459.5 ; R37.2@4729.94,6567.97 4758.9,6567.97 v1(4759.15,6567.71) ; R59.2@4877.33,6920.43 v1(4877.33,6954.41) ; R60.2@4878.03,7163.78 v1(4878.03,7209.41)
  other v1: 4676.5,6189.41 3228.55,6199.41 3260.22,6199.41 3290,6199.41 3228.32,6224.41 3260,6224.41 3290,6224.41 4487.5,7272.46 3612.72,7340.91 3612.72,7399.73 4380,7419.41 4405.54,7419.41
DCDC2: C392.1 L2.2 U34.26 | length 358
  Top Layer w10: L2.2@3401.26,6020.47 3401.26,5984.84 3420.63,5965.47 3509.01,5965.47 3522.03,5978.49 3522.03,6082.26 3552.28,6112.5 3593.23,6112.5 U34.26@3593.74,6113.01
DCDC3: C6.1 L8.2 U34.4 | length 286.9
  Top Layer w10: U34.4@3789.36,6096.48 3828.71,6096.48 3859.73,6065.47 3859.73,5994.83 3874.09,5980.47 3965.63,5980.47 L8.2@3980.63,5995.47
DCDC4: C393.1 L4.2 U34.9 | length 290
  Top Layer w10: U34.9@3789.36,6175.22 3806.55,6175.22 3826.79,6195.46 3826.79,6230.22 3862.04,6265.47 3965.63,6265.47 3980,6251.1 L4.2@3980,6215.47
DCDC5/VSYS: C17.2 C18.2 L5.1
DCDC5_FB: U34.32
FLASH_CLK: U2.53 U35.6 | length 616.2
  Top Layer w10: U35.6@3480.02,7373.75 3480.02,7426.51 3511.16,7457.65 3700.59,7457.65 3817.46,7340.78 v1(3865.99,7340.78)
  Bottom Layer w10: v1(3865.99,7340.78) 3870.59,7340.78 3901.93,7372.11 U2.53@3901.93,7439.33
FLASH_CS: R55.2 U2.58 U35.1 | length 724.5
  Top Layer w10: U35.1@3580,7648.39 3580,7699.41 3595,7714.41 3615,7714.41 3625,7704.41 R55.2@3625,7674.41 3916.36,7674.41 3916.61,7674.16 3933.39,7674.16 3933.64,7674.41 v1(3961.86,7674.41)
  Bottom Layer w10: v1(3961.86,7674.41) 4000.35,7635.92 U2.58@4000.35,7439.33
FLASH_MISO: U2.54 U35.2 | length 735.3
  Top Layer w10: U35.2@3530,7648.39 3530,7709.41 3550,7729.41 3890,7729.41 v1(3925,7694.41)
  Bottom Layer w10: U2.54@3921.61,7439.33 3921.61,7691.02 v1(3925,7694.41)
FLASH_MOSI: U2.55 U35.5 | length 697.6
  Top Layer w10: U35.5@3430,7370.43 3430,7429.41 3472.24,7471.65 3706.39,7471.65 3813.63,7364.41 v1(3925,7364.41)
  Bottom Layer w10: v1(3925,7364.41) 3941.3,7380.71 U2.55@3941.3,7439.33
GBUF: CN2.3 U12.42 | length 1389.3
  Top Layer w10: CN2.3@3286.3,5366.34 3286.3,5333.11 3300,5319.41 3465,5319.41 v1(3485,5339.41)
  Bottom Layer w10: v1(3485,5339.41) 3525,5379.41 3865,5379.41 3925,5439.41 3925,5554.41 3990,5619.41 4345,5619.41 4374.84,5649.25 U12.42@4374.84,5707.09
GND: C4.2 C5.2 C6.2 C11.2 C12.2 C13.2 C14.2 C15.2 C16.2 C17.1 C18.1 C19.1 C20.1 C21.1 C22.1 C23.1 C24.1 C25.1 C26.1 C27.1 C28.1 C34.1 C35.1 C36.1 C342.1 C343.1 C346.1 C347.1 C348.2 C349.2 C350.1 C351.1 C359.1 C361.1 C367.1 C368.1 C369.1 C370.1 C371.1 C372.1 C373.1 C374.1 C375.1 C376.1 C377.1 C378.1 C379.1 C383.2 C384.2 C385.2 C391.2 C392.2 C393.2 C394.2 C395.2 C396.2 C397.2 C398.1 C400.1 C402.1 C403.1 CARD2.6 CARD2.10 CARD2.11 CARD2.12 CARD2.13 CN5.1 CN5.5 CN5.6 FPC1.1 FPC1.6 FPC1.7 FPC1.8 lcd1.5 lcd1.34 lcd1.38 lcd1.39 pad.31 Q1.2 Q5.2 R3.2 R4.2 R7.1 R29.1 R56.1 R57.2 touch1.6 touch1.7 touch1.8 U2.24 U2.49 U2.78 U2.79 U2.96 U6.2 U10.1 U11.1 U12.4 U12.16 U12.20 U12.21 U12.22 U12.35 U12.37 U12.40 U12.41 U12.47 U23.7 U29.4 U32.1 U33.1 U33.3 U33.4 U34.3 U34.41 U35.4 U36.3 U36.4 U37.1 U38.1 USBC1.0 USBC1.A1 USBC1.A12 USBC1.B1 USBC1.B12 X2.2 X2.4 X3.2 X3.4 | length 2601.1
  Top Layer w10: 3410,6266.17 3441.97,6266.17 C395.2@3470.69,6294.89 ; U34.41@3742.93,6080.72 3743.17,6080.48 U34.3@3782.45,6080.48
  Bottom Layer w10: C379.1@3445,6934.41 3442.5,6936.91 v1(3426.85,6936.91) v1(3400,6936.91) v1(3400,6909.75) v1(3400,6882.71) v1(3400,6855.68) v1(3400,6829.1) 3400,6814.41 v1(3410,6804.41) v1(3435.22,6804.41) v1(3460.18,6804.41) v1(3485.65,6804.41) v1(3510.61,6804.41) v1(3537.12,6804.41) v1(3561.56,6804.41) v1(3587.5,6804.41) 3595,6811.91 v1(3595,6828.64) v1(3595,6854.64) v1(3595,6879.59) v1(3595,6905.99) 3595,6934.41 C378.1@3550,6934.41 ; C36.1@3670.63,7389.41 3680.63,7379.41 v1(3690,7379.41) ; X3.4@4131.69,6257.91 4127.7,6253.92 4080,6253.92 ; C350.1@4145,6154.41 4154.75,6164.16 v1(4154.75,6182.95) v1(4154.75,6210.26) 4145.6,6219.41 v1(4126.74,6219.41) 4087.07,6219.41 4080,6226.48 v1(4080,6239.38) 4080,6253.92 ; C4.2@4200,7539.41 v1(4179.63,7539.41) 4162.93,7539.41 v1(4162.93,7557.49) v1(4162.93,7583.71) v1(4162.93,7610.49) v1(4162.93,7643.26) v1(4162.93,7669.47) v1(4162.93,7698.53) 4162.93,7715.44 v1(4185.32,7715.44) v1(4212.68,7715.44) v1(4239.74,7715.44) v1(4267.95,7715.44) v1(4294.45,7715.44) v1(4321.8,7715.44) 4343.1,7715.44 4348.44,7710.1 ; X3.2@4218.31,6320.9 4272.87,6320.9 4275,6323.03 ; C351.1@4250,6154.41 4240,6164.41 v1(4240,6183.79) v1(4240,6210.71) 4241.3,6210.71 4257.07,6226.48 v1(4267.93,6226.48) 4275,6233.55 v1(4275,6253.71) v1(4275,6281.52) v1(4275,6307.93) 4275,6323.03 ; v1(4285.71,5639.66) 4286.08,5640.03 C348.2@4302.08,5640.03 ; C385.2@4310,7539.41 4345,7539.41 ; C384.2@4375,7539.41 4345,7539.41 ; v1(4405,5754.16) 4414.21,5744.95 U12.40@4414.21,5707.09 ; C383.2@4490,7539.41 4542.07,7539.41 v1(4542.07,7568.71) v1(4542.07,7599.85) v1(4542.07,7630.41) v1(4542.07,7658.28) v1(4542.07,7686.54) v1(4542.07,7714.41) v1(4514,7714.41) v1(4485.75,7714.41) v1(4454.61,7714.41) v1(4426.93,7714.41) v1(4395.79,7714.41) v1(4367.92,7714.41) 4352.75,7714.41 4348.44,7710.1 ; 4080,6253.92 v1(4080,6268.88) v1(4080,6295.29) v1(4080,6323.1) v1(4080,6349.41) 4090,6359.41 v1(4103.98,6359.41) v1(4137.14,6359.41) v1(4171.41,6359.41) v1(4203.73,6359.41) v1(4235.48,6359.41) v1(4265,6359.41) 4275,6349.41 v1(4275,6336.87) 4275,6323.03 ; 4345,7539.41 v1(4345,7632.43) v1(4345,7663.48) 4345,7706.66 4348.44,7710.1
  other v1: 3197.09,5432.19 3197.09,5501.81 3197.09,5555.61 4080,5709.41 3805,5787.98 3755,5824.41 3805,5824.41 4700,5834.41 3215,5849.41 4700,5864.41 4606.03,5869.41 4766.87,5925.36 3315,5934.41 3275,5997.34 3275,6044.41 3275,6084.41 4315,6084.41 4375.67,6097.54 4190,6099.41 4170,6119.41 4360,6119.41 4340,6139.41 4275,6144.66 4305,6144.66 4095.55,6219.41 3385,6264.41 4758.5,6309.07 4900,6554.8 4900,6594.41 4900,6629.41 3275,6724.41 3525,6729.41 3552.28,6960.49 3455,6964.41 3470,6984.41 3570,6984.41 3225,7094.41 3895,7134.41 3925,7134.41 3955,7134.41 4015,7134.41 3985.68,7135.09 3225,7149.41 3225,7209.41 4125,7229.41 3225,7279.41 4590,7299.41 4098.78,7305.23 4585,7339.41 3225,7344.41 4182.1,7371.56 4510,7374.41 4405,7379.41 4585,7379.41 4455,7384.41 4515,7411.61 4465,7414.41 4515,7444.41 4460,7454.41 4440,7479.41 4375,7484.16 4505,7484.41 4411.82,7497.59 4130,7509.16 4485,7509.41 4435,7514.41 4380,7569.41 4439.75,7569.41 4480.25,7574.41 4343.87,7578.45 4439.75,7594.6 4380,7596.77 4490,7604.41 4343.87,7605.08 3975,7764.41 4041.16,7764.41 4102.87,7764.41 4185,7764.41
  other v2: 3663.44,6092.84 3690.96,6092.84 3718.36,6092.84 3663.44,6120.1 3690.96,6120.1 3718.36,6120.1 3663.44,6147.84 3690.96,6147.84 3718.36,6147.84
GPIO: R29.2 U12.33 U12.34 | length 191
  Bottom Layer w10: U12.34@4532.32,5805.51 4485,5805.51 4480,5810.51 4480,5819.41 4485.79,5825.2 U12.33@4532.32,5825.2 4533.11,5824.41 R29.2@4605,5824.41
I/O: R42.1 U2.51 U29.6 | length 576.5
  Bottom Layer w10: U29.6@3500.92,7273.17 3500.92,7381.41 3597.12,7477.61 3733.03,7477.61 3782.36,7526.94 3847.31,7526.94 3862.41,7511.84 U2.51@3862.41,7471.62
IM0: lcd1.11 R3.1 R52.1 | length 474.8
  Top Layer w10: lcd1.11@4182.74,7017.44 4182.32,7017.01 4182.32,6973.81 4264.6,6891.54 4565.11,6891.54 R52.1@4575.11,6901.54
IRQ: U34.38
LCD_CS: lcd1.7 U2.44 | length 607.9
  Top Layer w10: v1(4232.96,7152.37) 4261.22,7124.11 lcd1.7@4261.22,7042.64
  Bottom Layer w10: U2.44@3783.82,7242.48 3931.93,7242.48 3996.61,7177.8 4207.53,7177.8 v1(4232.96,7152.37)
LCD_RD: lcd1.10 U2.60 | length 465
  Top Layer w10: v1(4040,7234.41) 4191.24,7083.17 4192.94,7083.17 4199.38,7076.72 4199.38,7075.03 4202.16,7072.24 lcd1.10@4202.16,7042.64
  Bottom Layer w10: U2.60@4039.72,7439.33 4040,7439.06 v1(4040,7234.41)
LCD_RS: lcd1.8 U2.66 | length 431.4
  Top Layer w10: v1(4158.64,7198.05) 4241.53,7115.15 lcd1.8@4241.53,7042.64
  Bottom Layer w10: U2.66@4157.83,7439.33 4157.83,7198.85 v1(4158.64,7198.05)
LCD_RST: lcd1.31 U2.65 | length 625.3
  Top Layer w10: lcd1.31@3788.78,7042.64 3787.28,7044.14 3787.28,7181.69 3970,7364.41 v1(4079.66,7364.41)
  Bottom Layer w10: v1(4079.66,7364.41) 4111.14,7364.41 4138.15,7391.42 U2.65@4138.15,7439.33
LCD_WR: lcd1.9 U2.61 | length 464
  Top Layer w10: v1(4071.82,7231.23) 4221.85,7081.2 lcd1.9@4221.85,7042.64
  Bottom Layer w10: U2.61@4059.41,7439.33 4059.41,7243.64 v1(4071.82,7231.23)
LED_K: lcd1.17 lcd1.18 lcd1.19 lcd1.20 R5.2 | length 294.4
  Top Layer w10: lcd1.20@4005.32,7042.64 4005.32,6991.09 4015,6981.41 4024.69,6981.41 ; lcd1.19@4025.01,7042.64 4025.01,6981.73 4024.69,6981.41 ; lcd1.18@4044.68,7042.64 4044.68,6982.12 4045.39,6981.41 ; lcd1.17@4064.38,7042.64 4064.38,6988.78 4057,6981.41 4045.39,6981.41 ; 4024.69,6981.41 4045.39,6981.41
LEFT: C352.2 CN2.5
LINE: C400.2 R58.1 U12.1 | length 581.2
  Bottom Layer w10: R58.1@3827.08,5409.31 3827.08,5431.49 3895,5499.41 3895,5584.41 4076.73,5766.14 U12.1@4197.68,5766.14
MICN: FPC1.3 FPC1.4 U12.2 | length 571.6
  Top Layer w10: v1(4337.66,5811.81) 4422.6,5811.81 4485,5749.41 4630,5749.41 ; FPC1.3@4674.31,5739.57 4634.84,5739.57 4630,5744.41 4630,5749.41 ; FPC1.4@4674.31,5759.25 4634.84,5759.25 4630,5754.41 4630,5749.41
  Bottom Layer w10: U12.2@4197.68,5785.83 4286.83,5785.83 4312.81,5811.81 v1(4337.66,5811.81)
MISO: CARD2.7 R24.1 U2.28 | length 1996.5
  Top Layer w10: v1(3565,7525.86) 3584.25,7525.86 3589.5,7531.11 3951.43,7531.11 4112.68,7369.87 4112.68,7355.73 4195.99,7272.41 4244.86,7272.41 4265.93,7293.48 R24.1@4265,7294.41 4325.08,7294.41 CARD2.7@4331.34,7288.15
  Bottom Layer w10: v1(3565,7525.86) 3545.75,7525.86 3540.5,7531.11 3441.5,7531.11 3358.4,7448.01 3358.4,7211.21 3414.2,7155.41 3619,7155.41 3653,7121.41 3653,6991.61 3713.33,6931.28 3780.05,6931.28 U2.28@3783.82,6927.52
MOSI: CARD2.3 R26.1 U2.29 | length 1909
  Top Layer w10: v1(3700,7565.36) 3963.65,7565.36 4079.6,7449.41 4241.86,7449.41 4252.72,7460.27 4265,7460.27 ; R26.1@4265,7474.41 4265,7460.27 ; CARD2.3@4331.34,7461.38 4266.11,7461.38 4265,7460.27
  Bottom Layer w10: v1(3700,7565.36) 3665.95,7565.36 3606.2,7505.61 3546.2,7505.61 3534.7,7517.11 3447.3,7517.11 3375,7444.81 3375,7214.41 3420,7169.41 3625,7169.41 3667,7127.41 3667,6997.41 3717.2,6947.2 U2.29@3783.82,6947.2
MP3_LEFT: C352.1 C358.1 U12.46 | length 1845.4
  Top Layer w10: C352.1@3521.39,5804.41 3564.4,5761.4 3898.01,5761.4 4019.75,5639.66 v1(4216.82,5639.66)
  Bottom Layer w10: v1(4216.82,5639.66) 4257.07,5639.66 4296.1,5678.69 U12.46@4296.1,5707.09 ; U12.46@4296.9,5731.77 4296.9,5745.6 4342.86,5791.56 4440.41,5791.56 4499.81,5732.16 4620.44,5732.16 4676.5,5788.23 4676.5,6095.8 4720.48,6139.77 4786.2,6139.77 4813.8,6167.38 C358.1@4813.8,6190.49
MP3_RIGHT: C353.1 U12.39 | length 911.3
  Top Layer w10: C353.1@3665,5715.8 3693.61,5744.41 3889.75,5744.41 v1(4035,5599.16)
  Bottom Layer w10: v1(4035,5599.16) 4369.75,5599.16 4433.9,5663.31 U12.39@4433.9,5707.09
PA0: U2.3
PA1: U2.4 U12.28 | length 1268.6
  Top Layer w10: v1(4600.81,5953.66) 4639.25,5953.66 4656.25,5970.66 v1(4656.25,5998.78)
  Bottom Layer w10: U2.4@4275.94,6809.41 4275.94,6743.46 4300,6719.41 4520,6719.41 4656.25,6583.16 v1(4656.25,5998.78) ; U12.28@4532.32,5923.62 4570.77,5923.62 v1(4600.81,5953.66)
PA2: U2.5 U12.30 | length 1282.2
  Bottom Layer w10: U2.5@4256.26,6809.41 4256.26,6743.15 4294,6705.41 4514.2,6705.41 4636,6583.61 4636,5940.41 4579.84,5884.25 U12.30@4532.32,5884.25
PA3: U2.6 U12.29 | length 1259
  Bottom Layer w10: U2.6@4236.57,6809.41 4236.57,6743.04 4288.2,6691.41 4508.4,6691.41 4622,6577.81 4622,5946.21 4579.73,5903.94 U12.29@4532.32,5903.94
PA4: U2.7 U12.23 | length 1160.7
  Bottom Layer w10: U2.7@4216.89,6809.41 4216.89,6742.92 4282.4,6677.41 4502.6,6677.41 4608,6572.01 4608,6167.41 4540,6099.41 4475,6099.41 4453.58,6077.99 U12.23@4453.58,6041.73
PA5: U2.8 U12.13 | length 1438.5
  Top Layer w10: v1(4425,5969.41) 4425,6139.41 4455,6169.41 4455,6229.18 v1(4574.75,6348.93)
  Bottom Layer w10: U2.8@4197.2,6809.41 4197.2,6742.81 4276.6,6663.41 4496.8,6663.41 4574.75,6585.46 v1(4574.75,6348.93) ; U12.13@4256.73,6041.73 4256.73,5972.68 4275,5954.41 4410,5954.41 v1(4425,5969.41)
PA6: U2.9 U12.8 | length 1493.9
  Top Layer w10: v1(4290,5904.41) 4484.08,5904.41 4540,5960.33 v1(4540,6204.41)
  Bottom Layer w10: U2.9@4177.52,6809.41 4177.52,6742.69 4270.8,6649.41 4491.01,6649.41 4540,6600.41 v1(4540,6204.41) ; U12.8@4197.68,5903.94 4289.53,5903.94 v1(4290,5904.41)
PA7: U2.10 U12.3 | length 1632
  Top Layer w10: v1(4322.34,5845.36) 4527.8,5845.36 4575,5892.56 4575,6203.05 4519.75,6258.3 v1(4519.75,6260.41)
  Bottom Layer w10: U2.10@4157.83,6809.41 4157.83,6742.58 4265.01,6635.41 4485.21,6635.41 4519.75,6600.87 v1(4519.75,6260.41) ; U12.3@4197.68,5805.51 4201.06,5808.88 4228.65,5808.88 4265.12,5845.36 v1(4322.34,5845.36)
PA8: U2.11
PB4: U2.30
PB5: U2.31
PB6: U2.32
PB7: U2.33
PB8: R2.1 touch1.4 U2.34 | length 2669.7
  Top Layer w10: v1(3680,7149.41) 3657.4,7172.01 3432.4,7172.01 3369,7108.61 3369,6760.21 3444.8,6684.41 4495,6684.41 4545.82,6633.59 4545.82,6461.56 4482.2,6397.94 4413.53,6397.94 4390,6374.41 R2.1@4390,6329.41 4390,6264.41 4375,6249.41 4375,6185.26 touch1.4@4374.84,6185.1
  Bottom Layer w10: v1(3680,7149.41) 3681,7148.41 3681,7083.41 3720,7044.41 3782.6,7044.41 U2.34@3783.82,7045.63
PB9: touch1.5 U2.35 | length 1979.4
  Top Layer w10: touch1.5@4394.53,6185.1 4394.53,6238.94 4415,6259.41 v1(4415,6279.41)
  Inner1 w10: v1(3645,6859.41) 3645,7064.41 3670,7089.41 v1(3710.25,7089.41)
  Bottom Layer w10: v1(3645,6859.41) 3645,6739.41 3495,6589.41 3495,6504.41 3545,6454.41 4380,6454.41 4415,6419.41 v1(4415,6279.41) ; v1(3710.25,7089.41) 3710.25,7089.16 3734.09,7065.31 U2.35@3783.82,7065.31
PB12: U2.38
PB13: U2.39
PB14: U2.40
